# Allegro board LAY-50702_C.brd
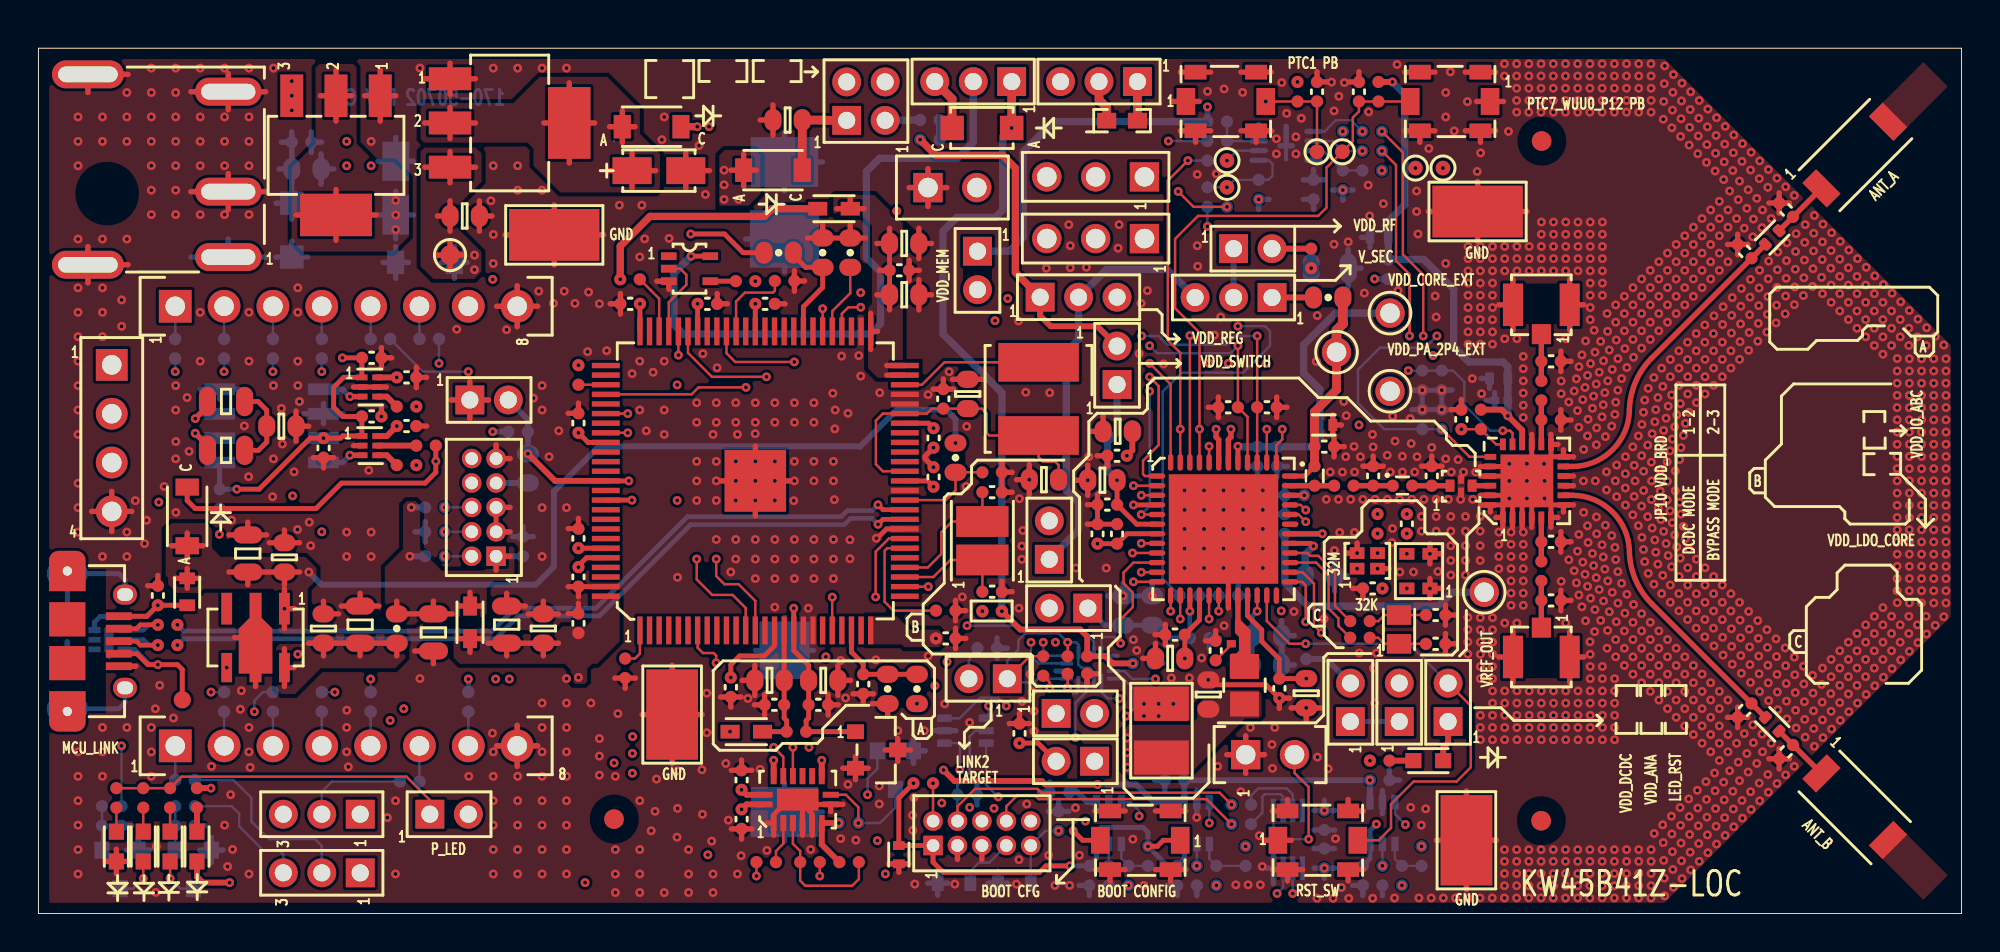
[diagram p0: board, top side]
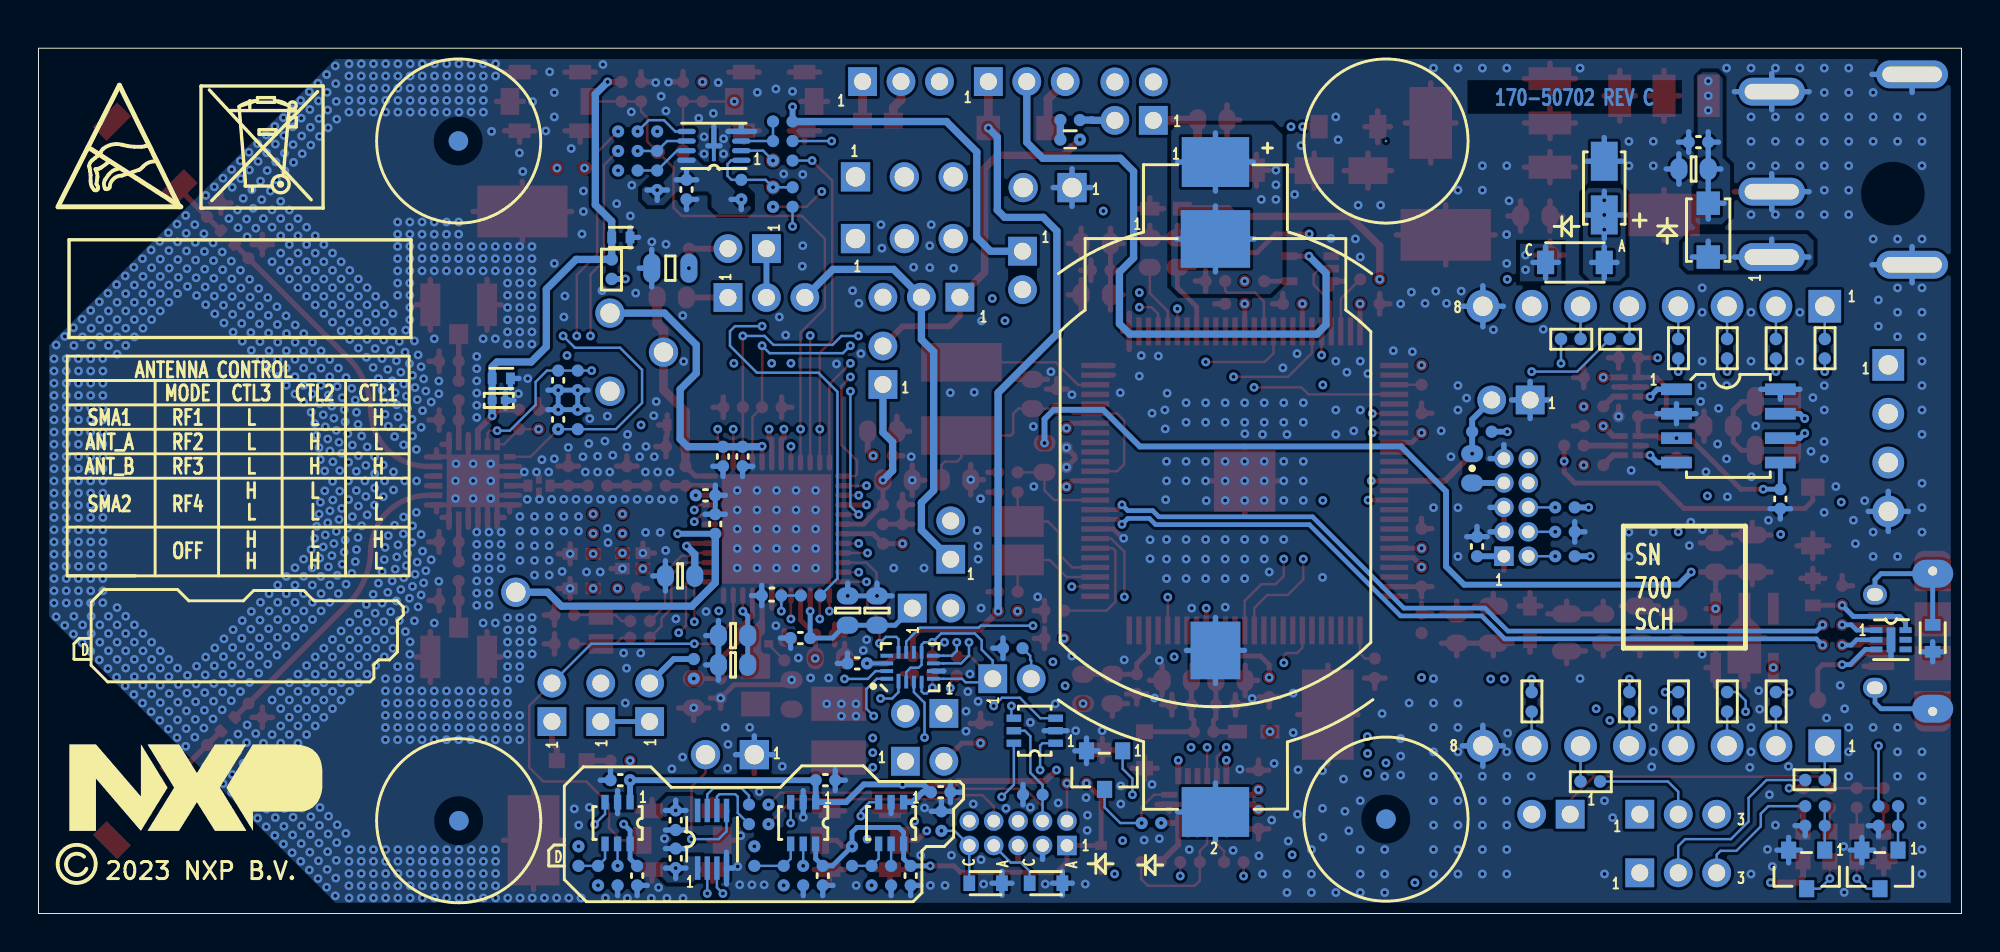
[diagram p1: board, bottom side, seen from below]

Outline 100 x 45 mm; copper layers: TOP, L2_GND_1, L3_INT_1, L4_INT_2, L5_GND_2, BOTTOM. Coordinates in mm from the lower left corner of the outline.
Outline path: 0,45 0,0 100,0 100,45 0,45

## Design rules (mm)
constraint set DEFAULT: min track width 0.127
net group CAN_H&L_DP_100_OHM: nets CAN_HI CAN_LO
net group CAN_RX&TX_DP_100_OHM: nets CAN_RX CAN_TX
net group CAN_XTND_RX&TX_DP_100_OHM: nets PTC4 PTC5
net group EXTAL32_DP: nets PTD4_XTAL32K PTD5_EXTAL32K
net group USB_DP_90_OHM: nets FL_USB1_DM FL_USB1_DP
net group XTAL_RF_DP: nets EXTAL_RF XTAL_RF

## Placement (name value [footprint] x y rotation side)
BMP1  BUMPER_312MIL  [BUMPER_RD_312MIL]  29.93 40.17 180 bottom
BMP2  BUMPER_312MIL  [BUMPER_RD_312MIL]  78.15 40.17 180 bottom
BMP3  BUMPER_312MIL  [BUMPER_RD_312MIL]  29.93 4.91 180 bottom
BMP4  BUMPER_312MIL  [BUMPER_RD_312MIL]  78.15 4.83 180 bottom
BT1  SMTU2450N-LF  [CON2_BH_CR2430]  38.8 22.18 270 bottom
BT2  S8421-45R  [BATTERY_HOLDER_2032_SM]  38.8 22.18 0 bottom
C1  1.1pF  [CC0402_25]  69.4 22.76 90 top
C2  2.5pF  [CC0402_25]  72.45 22.76 90 top
C3  15pF  [CC0402_ALT_NSP]  73.98 22.25 0 top
C5  22uF  [CC1210]  58.39 9.51 90 top
C6  0.01uf  [CC0603_OV]  60.83 11.39 90 top
C7  1uF  [CC0402_TOL0P2]  66.83 25.41 0 top
C8  47pF  [CC0402_25]  61.21 13.68 90 top
C9  10PF  [CC0402_25]  88.72 34.44 135 top
C10  1pF  [CC0402_25]  90.87 36.59 135 top
C11  10PF  [CC0402_25]  88.72 10.56 225 top
C12  1pF  [CC0402_25]  90.87 8.41 225 top
C13  4.7uF  [CC0603_OV]  58.85 13.27 180 top
C14  0.1UF  [CC0402_25]  59.1 14.51 180 top
C15  0.22uF  [CC0402_25]  64.81 20.26 90 bottom
C16  0.1UF  [CC0402_25]  63.39 23.77 270 bottom
C17  0.1UF  [CC0402_25]  64.4 23.77 270 bottom
C18  12pF  [CC0402_25]  66.86 24.28 0 top
C19  0.01uF  [CC0201]  76.06 26.69 180 bottom
C20  1uF  [CC0402_TOL0P2]  75.93 27.83 180 bottom
C21  3pF  [CC0402_25]  63.88 26.33 0 top
C22  3pF  [CC0402_25]  61.86 26.33 180 top
C23  10uF  [CC0603_OV]  22.16 36.27 0 top
C24  10UF  [CC3216]  32.26 38.63 0 top
C25  10uF  [CC0603_OV]  38.96 41.27 180 top
C26  0.1UF  [CC0402_25]  55.58 21.27 180 top
C27  4.7uF  [CC0603_OV]  55.33 22.54 180 top
C28  0.1UF  [CC0402_25]  56.09 19.74 90 top
C29  0.1UF  [CC0402_25]  55.07 19.74 90 top
C30  10uF  [CC0603_OV]  65.92 11.46 270 top
C31  0.1UF  [CC0402_25]  64.53 11.71 270 top
C32  4.7uF  [CC0603_OV]  56.12 25.08 180 top
C33  0.1UF  [CC0402_25]  56.09 23.81 180 top
C34  4.7uF  [CC0603_OV]  66.63 17.56 0 bottom
C35  0.1UF  [CC0402_25]  60.38 14.33 0 bottom
C36  4.7uF  [CC0603_OV]  57.92 15.76 90 bottom
C37  10uF  [CC0603_OV]  56.4 15.76 90 bottom
C38  4.7uF  [CC0603_OV]  63.88 12.93 0 bottom
C39  1.5uF  [CC0603_OV]  63.88 14.45 0 bottom
C40  12pF  [CC0402_25]  65.31 21.75 180 bottom
C41  22uF  [CC0805_OV]  67.14 33.56 0 bottom
C42  10uF  [CC0402_TOL0P2]  69.72 35.16 180 bottom
C43  1000pF  [CC0402_25]  61.88 16.54 0 bottom
C44  0.1UF  [CC0402_25]  66.3 37.65 270 bottom
C45  1000pF  [CC0402_25]  66.48 42.74 90 top
C46  1000pF  [CC0402_25]  68.67 42.74 90 top
C47  0.1UF  [CC0402_25]  69.38 16.91 180 top
C48  1000pF  [CC0402_25]  71.16 20.27 270 top
C49  12pF  [CC0402_25]  72.66 14.03 0 top
C50  12pF  [CC0402_25]  72.66 15.53 0 top
C51  4.7uF  [CC0603_OV]  26.25 14.82 90 top
C52  0.1UF  [CC0402_25]  34.78 31.71 0 top
C53  10uF  [CC0805_OV]  20.54 14.62 270 top
C54  10uF  [CC0805_OV]  24.35 15.03 90 top
C55  0.1UF  [CC0402_25]  36 11.77 270 top
C56  0.1UF  [CC0402_25]  47.18 14.31 0 top
C57  0.1UF  [CC0402_25]  46.54 24.73 270 top
C58  0.1UF  [CC0402_25]  37.78 31.71 0 top
C59  0.01UF  [CC0402_25]  30.77 31.71 180 top
C60  0.01UF  [CC0402_25]  28.08 25.51 90 top
C61  0.01UF  [CC0402_25]  28.08 19.51 90 top
C62  0.01UF  [CC0402_25]  28.08 15.09 90 top
C63  0.1UF  [CC0402_25]  38.27 10.86 180 top
C64  47pF  [CC0603_OV]  38.01 12.13 180 top
C65  47pF  [CC0603_OV]  48.32 27.02 90 top
C66  0.1UF  [CC0402_25]  47.05 26.77 90 top
C67  22uF  [CC0603_OV]  52.28 22.56 180 top
C68  22uF  [CC0603_OV]  45.02 34.85 0 top
C69  0.1UF  [CC0402_25]  44.77 33.45 0 top
C70  0.1UF  [CC0402_25]  40.55 10.86 0 top
C71  0.01uf  [CC0603_OV]  40.81 12.13 0 top
C72  47pF  [CC0603_OV]  45.02 32.18 0 top
C73  0.022UF  [CC0603_OV]  14.82 14.82 90 top
C74  10uF  [CC0805_OV]  16.73 15.03 90 top
C75  10uF  [CC0805_OV]  10.88 18.72 90 top
C76  0.022UF  [CC0603_OV]  12.79 18.52 90 top
C77  12pF  [CC0402_25]  49.59 21.91 0 top
C78  12pF  [CC0402_25]  49.59 16.74 0 top
C79  0.1UF  [CC0402_25]  46.54 22.7 90 top
C80  0.1UF  [CC0402_25]  28.08 17.51 270 top
C81  2.2UF  [CC0402_25]  6.21 16.54 90 top
C82  0.1UF  [CC0402_25]  42.89 11.93 270 top
C83  0.1UF  [CC0402_25]  25.19 19.09 90 bottom
C84  0.1UF  [CC0402_25]  57.42 13.01 0 bottom
C85  0.1UF  [CC0402_25]  66.86 4.85 270 bottom
C86  0.1UF  [CC0402_25]  66.86 2.87 90 bottom
C87  0.1UF  [CC0402_25]  53.09 6.31 180 bottom
C88  0.1UF  [CC0402_25]  54.65 1.97 270 bottom
C89  0.1UF  [CC0402_25]  69.74 6.94 0 bottom
C90  0.1UF  [CC0402_25]  68.87 1.97 270 bottom
C91  10uF  [CC0402_TOL0P2]  44.74 3.06 270 top
C92  0.1UF  [CC0402_25]  59.08 6.94 180 bottom
C93  0.1UF  [CC0402_25]  59.22 1.97 270 bottom
C94  0.1UF  [CC0402_25]  36.56 4.91 270 top
C95  0.1UF  [CC0402_25]  36.56 6.94 90 top
C97  10PF  [CC0402_25]  78.66 28.72 0 top
C98  10PF  [CC0402_25]  78.66 19.33 0 top
C99  10PF  [CC0402_25]  78.66 16.28 0 top
C100  100pF  [CC0402_25]  72.97 27.73 270 bottom
C101  100pF  [CC0402_25]  73.99 25.7 90 top
C102  100pF  [CC0402_25]  72.97 25.7 90 bottom
C103  0.1UF  [CC0402_25]  17.33 25.85 0 top
C104  0.1UF  [CC0402_25]  19.14 25.35 0 top
C105  0.1UF  [CC0402_25]  9.42 21.56 270 bottom
C106  0.1UF  [CC0402_25]  14.82 24.22 270 top
C107  10UF  [CC0603_OV]  13.93 38.72 0 bottom
C108  0.1UF  [CC0402_25]  13.68 40.12 0 bottom
C109  10UF  [CC3216]  18.58 37.73 90 bottom
C110  4700PF  [CC0603_OV]  12.63 25.35 180 top
C111  0.1UF  [CC0402_25]  17.33 28.9 0 top
C112  0.1UF  [CC0402_25]  19.14 27.88 0 top
C113  1000pF  [CC0402_25]  51.01 9.37 90 top
D1  RB160M-30  [PMDU_SOD123]  31.88 40.92 180 top
D2  RB160M-30  [PMDU_SOD123]  38.19 38.66 180 top
D3  SML-D14U2WT86C  [LED_0603]  72.27 7.95 0 top
D4  RB160M-30  [PMDU_SOD123]  7.73 20.65 270 top
D7  RED  [LED_0603]  8.24 3.49 270 top
D8  PNS40010ER  [SOD123W]  13.17 35.54 270 bottom
D12  PMEG1020EH  [SOD123LF]  49.06 40.85 0 top
D13  PESD3V3S1UB  [SOD523]  47.61 1.58 180 bottom
D14  PESD3V3S1UB  [SOD523]  50.75 1.58 180 bottom
D15  PESD3V3L5UY  [SOT-363_0P65_SMT]  48.19 9.51 0 bottom
D16  RB160M-30  [PMDU_SOD123]  20.1 33.86 180 bottom
E1  ANTENNA_2400MHZ  [ANTENNA-2450]  94.45 39.45 45 top
E2  ANTENNA_2400MHZ  [ANTENNA-2450]  94.45 5.55 315 top
J1  CON_1X8  [CON_1X8_SKT_2P54_TH]  7.11 31.58 90 top
J2  CON_1X8  [CON_1X8_SKT_2P54_TH]  7.11 8.72 90 top
J3  ZX62D-B-5PA8(30)  [CON9_MICROB_USB_SHELL_TH]  1.5 14.16 270 top
J4  HDR 2X5  [HDR205_50_TH]  23.8 18.58 90 top
J5  HDR 2X5  [HDR205_50_TH]  46.52 3.54 0 top
J7  20279-001E  [COAX_3P_SM_20279]  78.15 31.66 270 top
J8  20279-001E  [COAX_3P_SM_20279]  78.15 13.34 90 top
J9  CON PWR 3  [CON3_PWR_JACK_TH_PJ051A]  9.87 34.14 0 top
J10  HDR 1X4 RA  [CON_HDR_4M_100_TH_RA]  3.81 28.53 270 top
JP1  MTMM-102-06-G-S-236  [HDR102_TMM]  56.09 27.51 270 top
JP2  HDR 2X2  [HDR202_TMM]  42.03 41.25 0 top
JP3  HDR_1X3  [HDR103_78MIL]  52.09 32.05 180 top
JP4  MTMM-102-06-G-S-236  [HDR102_TMM]  54.56 15.88 0 top
JP6  MTMM-102-06-G-S-236  [HDR102_TMM]  62.15 34.58 180 top
JP7  MTMM-102-06-G-S-236  [HDR102_TMM]  68.22 9.98 270 top
JP8  MTMM-102-06-G-S-236  [HDR102_TMM]  52.56 18.42 270 top
JP9  MTMM-102-06-G-S-236  [HDR102_TMM]  70.76 9.98 270 top
JP10  HDR_1X3  [HDR103_78MIL]  64.15 32.04 0 top
JP11  MTMM-102-06-G-S-236  [HDR102_TMM]  73.3 9.98 270 top
JP12  MTMM-102-06-G-S-236  [HDR102_TMM]  22.43 26.71 180 top
JP13  HDR 1X3  [CONN_HDR_3X1]  57.51 35.1 270 top
JP14  HDR 1X3  [CONN_HDR_3X1]  57.51 38.31 270 top
JP16  MTMM-102-06-G-S-236  [HDR102_TMM]  54.92 7.92 0 top
JP17  MTMM-102-06-G-S-236  [HDR102_TMM]  50.38 12.21 0 top
JP18  HDR_1X3  [HDR103_78MIL]  50.61 43.27 0 top
JP19  HDR_1X3  [HDR103_78MIL]  57.15 43.27 0 top
JP21  HDR 1X2  [HDR102_338H]  46.25 37.75 90 top
JP22  HDR 1X2  [HDR102_338H]  62.77 8.26 90 top
JP23  HDR_1X3  [HDR103_78MIL]  16.73 2.12 0 top
JP24  HDR_1X3  [HDR103_78MIL]  16.73 5.17 0 top
JP25  MTMM-102-06-G-S-236  [HDR102_TMM]  52.92 10.41 180 top
JS1  HDR 1X2  [SH_HDR102_2MM_BOTTOM]  48.83 34.44 90 top
JS2  HDR 1X2  [SH_HDR102_2MM_BOTTOM]  20.35 5.17 180 top
L1  1uH  [IND_0805]  62.71 11.87 270 top
L2  15nH  [IND_0402_POL]  66.36 22.76 270 top
L3  0  [RC0402_25]  67.88 22.25 0 top
L4  600OHM  [IND_1P8X1MM_SM]  22.44 15.15 270 top
L5  600OHM  [IND_1P8X1MM_SM]  36.81 9.46 0 top
L6  4.7uH  [IND_5P2X5P2]  52 26.76 270 top
L7  600OHM  [IND_1P8X1MM_SM]  41.37 36.65 0 top
L8  330 OHM  [IND_1608]  7.73 16.73 90 top
L9  330 OHM  [IND_1608]  1.5 14.31 270 bottom
L10  1.5nH  [IND_0402_POL]  70.93 22.25 0 top
L11  2.2nH  [IND_0402_L]  90.16 35.16 45 top
L12  2.2nH  [IND_0402_L]  90.16 9.84 315 top
L13  1800 OHM  [IND_0402]  46.35 40.25 180 bottom
LED1  SML-D14U2WT86C  [LED_0603]  6.85 3.49 270 top
LED2  LED_YEL  [LED_0603]  5.45 3.49 270 top
LED3  LED_GREEN  [LED_0603]  4.05 3.49 270 top
NOREF  -  []  79.3 21.25 90 top
NOREF#2  -  []  79.45 20.45 0 top
NOREF#3  -  []  89.8 10.2 0 top
NOREF#4  -  []  30.9 14.17 0 top
NOREF#5  -  []  22.94 16.05 0 top
NOREF#6  -  []  41.2 5.68 90 top
NOREF#7  -  []  40.47 37.15 90 top
NOREF#8  -  []  66.36 25.41 0 top
NOREF#9  -  []  61.37 23.46 0 top
NOREF#10  -  []  38.67 37.15 0 top
NOREF#11  -  []  -349.15 214.49 0 top
NOREF#12  -  []  38.8 9.44 90 top
NOREF#13  -  []  68.1 2.28 90 top
NOREF#14  -  []  68.68 5.46 90 top
NOREF#15  -  []  64.45 3.81 0 top
NOREF#16  -  []  34.3 8 90 top
NOREF#17  -  []  6.2 17.91 90 top
NOREF#18  -  []  77.73 27.48 90 top
NOREF#19  -  []  90.01 9.78 0 top
NOREF#20  -  []  79.52 11.97 0 top
NOREF#21  -  []  40.73 4.71 90 top
NOREF#22  -  []  35.96 9.46 0 top
NOREF#23  -  []  61.37 23.46 0 top
NOREF#24  -  []  11.29 14.35 0 top
NOREF#25  -  [unnamed#2]  78.14 4.83 180 top
NOREF#26  -  []  76.53 27.48 0 top
NOREF#27  -  []  89.52 34.31 0 top
NOREF#28  -  []  70.75 14.03 90 top
NOREF#29  -  []  7.11 8.72 0 top
NOREF#30  -  []  55.72 5.34 0 top
NOREF#31  -  []  35.91 9.96 0 top
NOREF#32  -  []  13.59 15.65 0 top
NOREF#33  -  []  63.89 40.58 90 top
NOREF#34  -  []  44.39 3.66 0 top
NOREF#35  -  []  52 24.86 90 top
NOREF#36  -  []  64.95 2.28 0 top
NOREF#37  -  []  68.25 17.69 90 top
NOREF#38  -  []  73.98 21.93 90 top
NOREF#39  -  []  71.38 13.73 0 top
NOREF#40  -  []  76.67 31.66 0 top
NOREF#41  -  []  29.5 28.5 0 top
NOREF#42  -  []  78.15 14.87 0 top
NOREF#43  -  []  90.01 9.78 90 top
NOREF#44  -  []  71.26 37.28 90 top
NOREF#45  -  []  100 0 90 top
NOREF#46  -  []  71.52 34.81 90 top
NOREF#47  -  []  9.79 12.79 90 top
NOREF#48  -  []  60.17 40.71 0 top
NOREF#49  -  []  66.23 25.06 0 top
NOREF#50  -  []  35.91 8.96 90 top
NOREF#51  -  []  49.4 29.36 0 top
NOREF#52  -  []  61.31 4.26 90 top
NOREF#53  -  []  61.62 20 0 top
NOREF#54  -  []  45.69 2.4 0 top
NOREF#55  -  []  54.6 29.36 90 top
NOREF#56  -  []  62.77 8.26 0 top
NOREF#57  -  []  71.83 40.71 90 top
NOREF#58  -  []  23.8 18.58 90 top
NOREF#59  -  []  71.16 18.71 0 top
NOREF#60  -  []  58.39 4.26 0 top
NOREF#61  -  []  73.4 22.25 0 top
NOREF#62  -  []  55.15 -1.14 90 top
NOREF#63  -  []  38.23 7.15 0 top
NOREF#64  -  []  41.28 4.63 0 top
NOREF#65  -  []  82.27 11.97 90 top
NOREF#66  -  []  76.67 13.34 0 top
NOREF#67  -  []  68.25 17.69 0 top
NOREF#68  -  []  4.5 11.74 90 top
NOREF#69  -  []  45.69 2.4 90 top
NOREF#70  -  []  75.18 37.85 90 top
NOREF#71  -  []  18.19 15.65 90 top
NOREF#72  -  []  38.8 22.18 90 top
NOREF#73  -  []  72.36 16.91 90 top
NOREF#74  -  []  68.68 8.76 0 top
NOREF#75  -  []  79.52 33.03 90 top
NOREF#76  -  []  45.05 27 90 top
NOREF#77  -  []  58.16 19.75 90 top
NOREF#78  -  []  58.28 15.5 90 top
NOREF#79  -  []  78.65 20.6 90 top
NOREF#80  -  []  71.33 42.23 0 top
NOREF#81  -  []  66.96 37.28 0 top
NOREF#82  -  []  89.8 34.8 0 top
NOREF#83  -  []  4.18 12.86 90 top
NOREF#84  -  []  58.12 16.5 0 top
NOREF#85  -  []  46.25 37.75 0 top
NOREF#86  -  []  24.94 17.76 0 top
NOREF#87  -  []  32.2 34.92 0 top
NOREF#88  -  []  24.47 36.64 0 top
NOREF#89  -  []  68.57 17.94 0 top
NOREF#90  -  []  76.67 31.66 0 top
NOREF#91  -  []  38.8 13.68 90 top
NOREF#92  -  []  78.29 6.16 90 top
NOREF#93  -  []  50.25 36.29 90 top
NOREF#94  -  []  23.8 18.58 90 top
NOREF#95  -  []  75.5 23.75 0 top
NOREF#96  -  []  45.59 3.66 90 top
NOREF#97  -  []  22.44 14.3 90 top
NOREF#98  -  []  22.94 15.05 90 top
NOREF#99  -  []  75.6 6.16 0 top
NOREF#100  -  []  59.67 42.23 0 top
NOREF#101  -  []  -385.38 -304.33 0 top
NOREF#102  -  []  83.55 20.45 90 top
NOREF#103  -  []  67.43 25.06 90 top
NOREF#104  -  []  78.15 24.4 0 top
NOREF#105  -  []  -1.3 23.51 0 top
NOREF#106  -  []  9.42 32.24 0 top
NOREF#107  -  []  50.85 -1.14 0 top
NOREF#108  -  []  61.62 20 90 top
NOREF#109  -  []  27.16 36.64 90 top
NOREF#110  -  []  36.78 30.28 0 top
NOREF#111  -  []  98.41 35.04 0 top
NOREF#112  -  []  24.94 17.76 90 top
NOREF#113  -  []  44.74 2.59 90 top
NOREF#114  -  []  63.45 40.67 0 top
NOREF#115  -  []  63.32 40.71 90 top
NOREF#116  -  []  76.77 33.03 0 top
NOREF#117  -  []  75.46 27.83 0 top
NOREF#118  -  []  12.22 32.24 90 top
NOREF#119  -  [unnamed#2]  29.93 4.91 180 top
NOREF#120  -  []  38.23 7.15 0 top
NOREF#121  -  []  -0.57 -80.18 0 top
NOREF#122  -  []  55.22 3.81 0 top
NOREF#123  -  []  73.48 13.73 90 top
NOREF#124  -  []  70.32 34.81 0 top
NOREF#125  -  []  22.53 18.58 0 top
NOREF#126  -  []  31.61 8 0 top
NOREF#127  -  []  4.18 13.51 90 top
NOREF#128  -  []  73.45 21.98 0 top
NOREF#129  -  []  43.88 4.63 90 top
NOREF#130  -  []  89.52 34.31 90 top
NOREF#131  -  []  46.52 3.54 0 top
NOREF#132  -  []  7.11 8.72 0 top
NOREF#133  -  [unnamed#2]  78.16 40.17 180 top
NOREF#134  -  []  40.52 36.65 0 top
NOREF#135  -  []  0 45 0 top
NOREF#136  -  []  37.28 22.5 90 top
NOREF#137  -  []  69.24 35.16 0 top
NOREF#138  -  []  68.57 17.94 90 top
NOREF#139  -  []  74.5 21.98 90 top
NOREF#140  -  []  7.11 8.72 0 top
NOREF#141  -  []  71.83 43.76 0 top
NOREF#142  -  []  72.49 37.85 0 top
NOREF#143  -  []  65.12 16.5 90 top
NOREF#144  -  []  46.52 3.54 90 top
NOREF#145  -  []  59.59 40.58 0 top
NOREF#146  -  []  46.52 3.54 0 top
NOREF#147  -  []  55.72 2.28 90 top
NOREF#148  -  []  44.28 15.5 0 top
NOREF#149  -  []  44.79 39.21 0 top
NOREF#150  -  []  98.01 2.56 180 bottom
NOREF#151  -  []  91.55 36.69 180 bottom
NOREF#152  -  []  98.38 4.3 180 bottom
NOREF#153  -  []  98.97 36.75 180 bottom
NOREF#154  -  []  98.41 29.96 180 bottom
NOREF#155  -  [unnamed#2]  78.14 4.83 180 bottom
NOREF#156  -  [unnamed#2]  29.93 4.91 180 bottom
NOREF#157  -  [unnamed#2]  78.16 40.17 180 bottom
Q1  BSH111BK  [SOT23_A]  8.05 2.29 0 bottom
Q2  BSH111BK  [SOT23_A]  4.24 2.29 0 bottom
Q3  BSS138P  [SOT23_A]  44.56 7.46 0 bottom
R1  22  [RC0201]  62.37 14.03 180 top
R8  100  [RC0402_25]  59.85 16.54 180 bottom
R9  10K  [RC0402_25]  65.47 42.74 270 top
R10  10K  [RC0402_25]  67.83 40.17 270 bottom
R11  10K  [RC0402_25]  63.45 37.65 90 bottom
R12  0  [RC0402_25]  69.35 39.66 180 bottom
R13  0  [RC0402_25]  61.29 39.16 0 bottom
R14  0  [RC0402_25]  69.35 40.67 180 bottom
R15  0  [RC0402_25]  61.29 40.17 0 bottom
R16  0  [RC0402_25]  60.79 37.26 90 bottom
R17  10K  [RC0402_25]  69.68 42.74 270 top
R18  0  [RC0402_25]  69.35 38.64 180 bottom
R19  10K  [RC0402_25]  61.29 41.19 0 bottom
R20  10K  [RC0402_25]  67.83 38.13 90 bottom
R21  0  [RC0402_25]  61.8 37.26 90 bottom
R22  100  [RC0402_25]  6.85 6.01 270 top
R23  100  [RC0402_25]  5.45 6.01 270 top
R24  100  [RC0402_25]  69.74 7.95 0 top
R25  510  [RC0402_25]  4.05 6.01 270 top
R26  0  [RC0402_25]  7.62 5.58 180 bottom
R27  0  [RC0402_25]  3.81 5.58 0 bottom
R28  10K  [RC0402_25]  7.62 4.57 180 bottom
R29  10K  [RC0402_25]  3.81 4.57 180 bottom
R30  0  [RC0402_25]  68.72 14.34 0 top
R31  0  [RC0402_25]  68.72 15.21 0 top
R32  0  [RC0402_25]  69.63 20.27 270 top
R33  1K  [RC0402_25]  39.41 9.46 0 top
R34  0  [RC0603_OV]  18.63 14.82 90 top
R37  10K  [RC0603_OV]  47.69 23.71 270 top
R38  0  [RC0603_OV]  40.78 34.37 270 top
R39  0  [RC0402_25]  6.72 15.02 0 top
R40  0  [RC0402_25]  6.72 13.96 0 top
R41  20K  [RC0402_25]  49.59 22.94 0 top
R42  0  [RC0603_OV]  38.49 34.37 180 top
R43  2.0K  [RC0603_OV]  45.68 11.68 90 top
R44  2.0K  [RC0603_OV]  44.16 11.68 270 top
R45  60.4  [RC0805_OV]  9.75 24.09 0 top
R46  100K  [RC0402_25]  20.62 21.12 0 bottom
R47  100K  [RC0402_25]  20.62 18.58 0 bottom
R48  100K  [RC0402_25]  24.94 25.06 0 bottom
R50  510  [RC0402_25]  8.24 6.01 270 top
R51  0  [RC0603_OV]  25.45 23.15 270 bottom
R53  100K  [RC0402_25]  20.62 19.85 180 bottom
R63  10  [RC0402_25]  62.55 5.67 180 bottom
R64  10  [RC0402_25]  62.55 4.65 180 bottom
R65  0  [RC0402_25]  52.25 12.87 90 top
R66  100K  [RC0402_25]  54.03 12.47 0 top
R67  100K  [RC0402_25]  54.03 13.38 0 top
R68  160K  [RC0402_25]  57.69 2.99 270 bottom
R69  100  [RC0402_25]  56.68 1.97 270 bottom
R70  2.2K  [RC0402_25]  55.66 1.97 270 bottom
R71  10  [RC0402_25]  49.34 13.8 0 bottom
R72  100K  [RC0402_25]  71.92 2.99 270 bottom
R73  100  [RC0402_25]  70.9 1.97 270 bottom
R74  2.2K  [RC0402_25]  69.89 1.97 270 bottom
R75  10K  [RC0402_25]  46.01 6.77 0 top
R76  100K  [RC0402_25]  62.77 2.99 270 bottom
R77  2.2K  [RC0402_25]  53.05 4.81 90 bottom
R78  100  [RC0402_25]  61.25 1.97 270 bottom
R79  10K  [RC0402_25]  48.3 6.18 0 bottom
R80  2.2K  [RC0402_25]  60.23 1.97 270 bottom
R81  1K  [RC0402_25]  28.08 28.01 90 top
R83  1K  [RC0402_25]  36.77 32.89 0 top
R84  100  [RC0402_25]  37.84 2.68 180 top
R85  100  [RC0402_25]  40.12 2.68 0 top
R86  10K  [RC0402_25]  42.13 4.71 0 bottom
R89  0  [RC0603_OV]  67.07 32.04 180 top
R91  100K  [RC0402_25]  75.01 25.7 270 top
R92  0  [RC0402_25]  78.15 27.19 90 top
R93  0  [RC0402_25]  78.15 17.81 270 top
R94  100K  [RC0402_25]  71.96 27.73 270 bottom
R95  100K  [RC0402_25]  71.96 25.7 90 bottom
R96  0  [RC0603_OV]  42.21 34.37 90 top
R97  4.7K  [RC0402_25]  20.16 24.33 180 top
R98  0  [RC0402_25]  19.14 23.32 0 top
R99  60.4  [RC0805_OV]  9.75 26.63 180 top
R100  0  [RC0402_25]  19.14 26.37 0 top
R101  100K  [RC0402_25]  42.15 2.68 0 top
R102  1K  [RC0402_25]  30.76 32.98 180 top
R104  1K  [RC0402_25]  38.8 32.9 0 top
R105  1K  [RC0402_25]  30.51 12.75 270 top
R106  1K  [RC0402_25]  47.18 15.75 0 top
R107  10  [RC0402_25]  46.35 41.27 0 bottom
R108  3.3  [RC0402_25]  65.92 12.73 270 bottom
R109  3.3  [RC0402_25]  66.18 34.07 270 top
R110  50  [RC0402_25]  78.66 25.67 0 top
SH1  0  [SH0402]  9.65 29.37 270 bottom
SH2  0  [SH0402]  7.11 29.37 270 bottom
SH3  0  [SH0402]  7.62 6.94 180 bottom
SH4  0  [SH0402]  12.19 29.37 270 bottom
SH5  0  [SH0402]  9.65 11.01 270 bottom
SH6  0  [SH0402]  14.73 29.37 270 bottom
SH7  0  [SH0402]  12.19 11.01 270 bottom
SH8  0  [SH0402]  17.78 29.88 0 bottom
SH9  0  [SH0402]  14.73 11.01 270 bottom
SH10  0  [SH0402]  20.32 29.88 0 bottom
SH11  0  [SH0402]  17.27 11.01 270 bottom
SH12  0  [SH0402]  70.19 33.51 90 bottom
SH13  0  [SH0402]  19.3 6.87 0 bottom
SH14  0  [SH0402]  22.35 11.01 270 bottom
SH15  0  [SH0402]  49.59 15.72 0 top
SH19  0  [SH0603]  56.35 41.23 0 top
SW1  TL1015AF160QG  [SW2_SPST_4X3_SM]  66.53 3.81 0 top
SW2  TL1015AF160QG  [SW2_SPST_4X3_SM]  61.74 42.23 0 top
SW3  TL1015AF160QG  [SW2_SPST_4X3_SM]  73.41 42.23 180 top
SW4  TL1015AF160QG  [SW2_SPST_4X3_SM]  57.3 3.81 180 top
TP1  TESTLOOP_LP  [TEST_LOOP]  70.28 31.22 0 top
TP2  TESTLOOP_LP  [TEST_LOOP]  75.18 16.71 0 top
TP3  TESTLOOP_LP  [TEST_LOOP]  67.5 29.19 0 top
TP4  TESTLOOP_LP  [TEST_LOOP]  70.28 27.16 0 top
TP7  -  [TPAD_040]  21.4 34.24 0 top
TP8  -  [TPAD_030]  71.6 38.77 0 top
TP9  -  [TPAD_030]  66.48 39.62 180 top
TP10  -  [TPAD_030]  73.03 38.77 0 top
TP11  -  [TPAD_030]  61.8 37.77 0 top
TP12  -  [TPAD_030]  67.8 39.62 0 top
TP13  -  [TPAD_030]  61.8 39.16 180 top
TP15  TP_2P7X4P7  [TP_2P7X4P7MM]  74.25 3.81 180 top
TP16  TP_2P7X4P7  [TP_2P7X4P7MM]  32.95 10.35 0 top
TP17  TP_2P7X4P7  [TP_2P7X4P7MM]  26.82 35.29 270 top
TP18  TP_2P7X4P7  [TP_2P7X4P7MM]  74.84 36.51 270 top
TP21  TP_35MIL  [TESTPOINT_35MIL]  7.48 11.11 0 top
U1  KW45B41Z  [QFN_48_0P5_7X7_5P7EP]  61.62 20 0 top
U2  HSWA4-63DR  [QFN24_0P5_SQ4_EP2P75]  77.4 22.5 90 top
U4  NCP1117ST33T3G  [SOT223]  24.5 41.11 270 top
U5  AT25XE161D-MAHN-T  [UDFN8_0P5_3X2MM]  64.88 39.92 0 bottom
U6  LPC55S69JBD100  [HLQFP100_0P5_14X14]  37.28 22.5 90 top
U7  LM4040C30IDBZR  [SOT23-3]  43.58 8.51 270 top
U8  XC6227C331PR-G  [SOT89-5]  11.29 14.35 180 top
U9  RClamp0854P.TCT  [SLP1616P6]  3.67 14.24 270 bottom
U10  74LVC2T45DC  [SSOP8_DCU]  64.97 3.86 180 bottom
U11  NX3DV2567GU  [PQFN16_0P4_2P65X1P85]  54.68 12.81 180 bottom
U12  74LVC1T45GW,125  [SOT-363_0P65_SMT]  55.66 4.71 270 bottom
U13  74LVC1T45GW,125  [SOT-363_0P65_SMT]  69.89 4.71 270 bottom
U14  74LVC1T45GW,125  [SOT-363_0P65_SMT]  60.23 4.71 270 bottom
U15  74LVC1G07GW-Q100  [SC70-5]  33.86 33.54 270 top
U16  74AVC4TD245BQ  [DHVQFN16_0P5_3P6X2P6]  39.48 5.93 90 top
U17  74LVCH1T45  [UDFN6_1X1P5MM]  17.24 24.33 0 top
U18  NCP1117ST50T3G  [SOT223]  15.47 39.43 180 top
U19  TJA1057GT/3  [SO8_1P27_4X5]  12.12 25.36 180 bottom
U20  74LVCH1T45  [UDFN6_1X1P5MM]  17.24 27.38 0 top
U21  DEA102025LT-6313A1  [FILTER_1P05X0P55_SM_B]  73.98 22.25 0 top
Y1  32MHz  [XTAL4_1P6X1P2]  69.1 18.34 0 top
Y2  32.768 kHz  [XTAL2_2X1P2_SM]  70.75 14.78 90 top
Y3  32.00MHZ  [OSC4_2P1X1P7MM_SM]  71.76 17.81 90 top
Y4  16MHz  [XTAL2_3P3X2P6]  49.08 19.39 90 top

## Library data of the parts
BMP1-BMP4 = Bumper
BT1 BT2 = BATTERY
C1-C3 C5-C8 C10 C12-C18 C20-C23 C25-C95 C100-C108 C110-C113 = CAP_NP
C9 C11 C97-C99 = CAP_NP: tolerance: 5%
C19 = CAP_NP: Tolerance: TOLERANCE; User Part Number: 150-80313
C24 C109 = CAP_POL
D1 D2 D4 D12 D16 = DIODE_SCHTKY
D3 D7 LED1-LED3 = LED
D8 = DIODE
D13 D14 = DIODE_TVS
D15 = DIODE_ARRAY_5CH
E1 E2 = ANTENNA_2P4GHZ
J1 J2 = CONN_HDR_8X1
J3 = MICRO_USB_CONN_9PIN
J4 J5 = CONN_HDR_5X2
J7 J8 = UFL
J9 = DC_POWER_JACK_SHD
J10 = CONN_HDR_4X1
JP1 JP4 JP6-JP9 JP11 JP12 JP16 JP17 JP21 JP22 JP25 JS1 JS2 = CONN_HDR_2X1
JP2 = CONN_HDR_2X2
JP3 JP10 JP13 JP14 JP18 JP19 JP23 JP24 = CONN_HDR_3X1
L1 L4-L7 L11 L12 = INDUCTOR
L2 L10 = INDP
L3 R1 R8 R10 R12-R16 R18-R34 R37-R48 R50 R51 R53 R63-R81 R83-R85 R89 R91-R96 R98-R102 R104-R110 = RES
L8 L9 L13 = BEAD
Q1 Q2 = NMOS_2N7002BKW_3P
Q3 = MOSFET_N
R9 R11 R17 R97 = RES: tolerance: 1%
R86 = RES: tolerance: 5%
SH1-SH15 SH19 = RES_SHORT-2
SW1-SW4 = SW_SPNO_2P_GND6P
TP1-TP4 TP7-TP13 = TESTLOOP
TP15-TP18 = TEST_POINT
TP21 = T POINT R: Tolerance: TOLERANCE; User Part Number: 510-75618
U1 = KW45B41Z_48EP
U2 = HSWA4-63DR
U4 U18 = LD1117AS18
U5 = AT25XE161D_8P_EP
U6 = LPC55S69JB_HLQFP100
U7 = LM4040_SOT23
U8 = XC6227C_5P
U9 = RCLAMP1654P_NEW
U10 = 74LVC2T45DC_8P
U11 = NX3DV2567GU_XQFN_16P
U12-U14 U17 U20 = 74LVCH1T45_6P
U15 = 74AUP1G07GW
U16 = 74AVC4TD245BQ_DHVQFN16
U19 = TJA1057GT3_8P
U21 = B9014_4P
Y1 = XTAL_13
Y2 Y4 = XTAL
Y3 = O4-0

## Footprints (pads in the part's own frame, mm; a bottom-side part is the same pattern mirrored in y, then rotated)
ANTENNA-2450
  rect 1.016x1.803 smd: 1(-2.45,0) 2(2.45,0)
BATTERY_HOLDER_2032_SM
  rect 3.607x2.997 smd: 1(0,-12.9)
  rect 2.591x2.997 smd: 2(0,8.5)
BUMPER_RD_312MIL
  round 0.127 smd: 1(0,0)
CC0201
  rect 0.47x0.381 smd: 1(-0.343,0) 2(0.343,0)
CC0402_25
  round 0.635 smd: 1(-0.508,0) 2(0.508,0)
CC0402_ALT_NSP
  rect 0.457x0.635 smd: 1(-0.575,0) 2(0.575,0)
CC0402_TOL0P2
  rect 0.457x0.61 smd: 1(-0.475,0) 2(0.475,0)
CC0603_OV
  oval 0.889x1.143 smd: 1(-0.762,0) 2(0.762,0)
CC0805_OV
  oval 0.889x1.524 smd: 1(-0.965,0) 2(0.965,0)
CC1210
  rect 1.778x2.845 smd: 1(-1.397,0) 2(1.397,0)
CC3216
  rect 2.032x1.397 smd: 1(-1.397,0) 2(1.397,0)
COAX_3P_SM_20279
  rect 1.041x0.991 smd: 1(1.525,0)
  rect 2.21x1.041 smd: 2(0,1.475) 3(0,-1.475)
CON2_BH_CR2430
  rect 2.591x3.505 smd: 1(-16.9,0) 2(16.9,0)
CON3_PWR_JACK_TH_PJ051A
  round 0 hole 2.54 unplated: (-6.3,3.3)
  oval 3.454x1.448 hole 2.819x0.813: 1(0,0) 2(0,8.6) 3(0,3.4)
  oval 3.734x1.448 hole 3.099x0.813: SH1(-7.3,9.5) SH2(-7.3,-0.4)
CON9_MICROB_USB_SHELL_TH
  rect 1.778x1.88 smd: (-1.139,0) (1.139,0)
  rect 0.406x1.346 smd: 1(-1.3,2.677) 2(-0.65,2.677) 3(0,2.677) 4(0.65,2.677) 5(1.3,2.677)
  oval 1.041x1.245 hole 0.66x0.838: 6(-2.425,3) 7(2.425,3)
  custom 0.475x0.475 hole 1.499x0.813: 8(-3.65,0) 9(3.65,0)
CON_1X8_SKT_2P54_TH
  rect 1.702x1.702 hole 1.016: 1(0,0)
  round 1.702 hole 1.016: 2(0,-2.54) 3(0,-5.08) 4(0,-7.62) 5(0,-10.16) 6(0,-12.7) 7(0,-15.24) 8(0,-17.78)
CON_HDR_4M_100_TH_RA
  rect 1.651x1.651 hole 1.016: 1(0,0)
  round 1.651 hole 1.016: 2(2.54,0) 3(5.08,0) 4(7.62,0)
CONN_HDR_3X1
  rect 1.524x1.524 hole 1.016: 1(0,0)
  round 1.524 hole 1.016: 2(0,-2.54) 3(0,-5.08)
DHVQFN16_0P5_3P6X2P6
  rect 0.305x0.838 smd: 1(-0.25,1.719) 8(-0.25,-1.719) 9(0.25,-1.719) 16(0.25,1.719)
  rect 0.838x0.305 smd: 2(-1.219,1.25) 3(-1.219,0.75) 4(-1.219,0.25) 5(-1.219,-0.25) 6(-1.219,-0.75) 7(-1.219,-1.25) 10(1.219,-1.25) 11(1.219,-0.75) 12(1.219,-0.25) 13(1.219,0.25) 14(1.219,0.75) 15(1.219,1.25)
  rect 1.143x2.159 smd: 17(0,0)
FILTER_1P05X0P55_SM_B
  rect 0.457x0.305 smd: 1(-0.575,0) 3(0.575,0)
  rect 0.305x0.457 smd: 2(0,-0.325) 4(0,0.325)
HDR102_338H
  rect 1.524x1.524 hole 1.016: 1(0,0)
  round 1.524 hole 1.016: 2(0,-2.54)
HDR102_TMM
  rect 1.499x1.499 hole 0.889: 1(0,0)
  round 1.499 hole 0.889: 2(-2,0)
HDR103_78MIL
  rect 1.499x1.499 hole 0.889: 1(0,0)
  round 1.499 hole 0.889: 2(-2,0) 3(-4,0)
HDR202_TMM
  rect 1.499x1.499 hole 0.889: 1(0,0)
  round 1.499 hole 0.889: 2(0,2) 3(2,0) 4(2,2)
HDR205_50_TH
  rect 1.016x1.016 hole 0.66: 1(0,0)
  round 1.016 hole 0.66: 2(0,1.27) 3(1.27,0) 4(1.27,1.27) 5(2.54,0) 6(2.54,1.27) 7(3.81,0) 8(3.81,1.27) 9(5.08,0) 10(5.08,1.27)
HLQFP100_0P5_14X14
  rect 1.448x0.279 smd: 1(-7.775,6) 2(-7.775,5.5) 3(-7.775,5) 4(-7.775,4.5) 5(-7.775,4) 6(-7.775,3.5) 7(-7.775,3) 8(-7.775,2.5) 9(-7.775,2) 10(-7.775,1.5) 11(-7.775,1) 12(-7.775,0.5) 13(-7.775,0) 14(-7.775,-0.5) 15(-7.775,-1) 16(-7.775,-1.5) 17(-7.775,-2) 18(-7.775,-2.5) 19(-7.775,-3) 20(-7.775,-3.5) 21(-7.775,-4) 22(-7.775,-4.5) 23(-7.775,-5) 24(-7.775,-5.5) 25(-7.775,-6) 51(7.775,-6) 52(7.775,-5.5) 53(7.775,-5) 54(7.775,-4.5) 55(7.775,-4) 56(7.775,-3.5) 57(7.775,-3) 58(7.775,-2.5) 59(7.775,-2) 60(7.775,-1.5) 61(7.775,-1) 62(7.775,-0.5) 63(7.775,0) 64(7.775,0.5) 65(7.775,1) 66(7.775,1.5) 67(7.775,2) 68(7.775,2.5) 69(7.775,3) 70(7.775,3.5) 71(7.775,4) 72(7.775,4.5) 73(7.775,5) 74(7.775,5.5) 75(7.775,6)
  rect 0.279x1.448 smd: 26(-6,-7.775) 27(-5.5,-7.775) 28(-5,-7.775) 29(-4.5,-7.775) 30(-4,-7.775) 31(-3.5,-7.775) 32(-3,-7.775) 33(-2.5,-7.775) 34(-2,-7.775) 35(-1.5,-7.775) 36(-1,-7.775) 37(-0.5,-7.775) 38(0,-7.775) 39(0.5,-7.775) 40(1,-7.775) 41(1.5,-7.775) 42(2,-7.775) 43(2.5,-7.775) 44(3,-7.775) 45(3.5,-7.775) 46(4,-7.775) 47(4.5,-7.775) 48(5,-7.775) 49(5.5,-7.775) 50(6,-7.775) 76(6,7.775) 77(5.5,7.775) 78(5,7.775) 79(4.5,7.775) 80(4,7.775) 81(3.5,7.775) 82(3,7.775) 83(2.5,7.775) 84(2,7.775) 85(1.5,7.775) 86(1,7.775) 87(0.5,7.775) 88(0,7.775) 89(-0.5,7.775) 90(-1,7.775) 91(-1.5,7.775) 92(-2,7.775) 93(-2.5,7.775) 94(-3,7.775) 95(-3.5,7.775) 96(-4,7.775) 97(-4.5,7.775) 98(-5,7.775) 99(-5.5,7.775) 100(-6,7.775)
  rect 3.2x3.2 smd: 101(0,0)
IND_1P8X1MM_SM
  rect 0.991x0.711 smd: 1(-0.845,0) 2(0.845,0)
IND_5P2X5P2
  rect 2.007x4.191 smd: 1(-1.903,0) 2(1.903,0)
IND_0402
  round 0.635 smd: 1(-0.508,0) 2(0.508,0)
IND_0402_L
  rrect 0.483x0.635 smd: 1(-0.5,0) 2(0.5,0)
IND_0402_POL
  round 0.635 smd: 1(-0.508,0) 2(0.508,0)
IND_0805
  rect 1.295x1.499 smd: 1(-0.978,0) 2(0.978,0)
IND_1608
  rect 0.61x0.813 smd: 1(-0.7,0) 2(0.7,0)
LED_0603
  rect 0.838x0.787 smd: A(-0.775,0) C(0.775,0)
OSC4_2P1X1P7MM_SM
  rect 0.61x0.787 smd: 1(-0.9,-0.6) 2(0.9,-0.6) 3(0.9,0.6) 4(-0.9,0.6)
PMDU_SOD123
  rect 0.889x1.219 smd: A(1.525,0) C(-1.525,0)
PQFN16_0P4_2P65X1P85
  rect 0.203x0.762 smd: 1(-0.6,-0.724)
  rect 0.203x0.66 smd: 2(-0.2,-0.775) 3(0.2,-0.775) 4(0.6,-0.775) 9(0.6,0.775) 10(0.2,0.775) 11(-0.2,0.775) 12(-0.6,0.775)
  rect 0.66x0.203 smd: 5(1.21,-0.6) 6(1.21,-0.2) 7(1.21,0.2) 8(1.21,0.6) 13(-1.21,0.6) 14(-1.21,0.2) 15(-1.21,-0.2) 16(-1.21,-0.6)
QFN24_0P5_SQ4_EP2P75
  rect 0.61x0.305 smd: 1(-1.9,1.25) 2(-1.9,0.75) 3(-1.9,0.25) 4(-1.9,-0.25) 5(-1.9,-0.75) 6(-1.9,-1.25) 13(1.9,-1.25) 14(1.9,-0.75) 15(1.9,-0.25) 16(1.9,0.25) 17(1.9,0.75) 18(1.9,1.25)
  rect 0.305x0.61 smd: 7(-1.25,-1.9) 8(-0.75,-1.9) 9(-0.25,-1.9) 10(0.25,-1.9) 11(0.75,-1.9) 12(1.25,-1.9) 19(1.25,1.9) 20(0.75,1.9) 21(0.25,1.9) 22(-0.25,1.9) 23(-0.75,1.9) 24(-1.25,1.9)
  rect 2.743x2.743 smd: 25(0,0)
QFN_48_0P5_7X7_5P7EP
  oval 0.864x0.279 smd: 1(-3.463,2.75) 2(-3.463,2.25) 3(-3.463,1.75) 4(-3.463,1.25) 5(-3.463,0.75) 6(-3.463,0.25) 7(-3.463,-0.25) 8(-3.463,-0.75) 9(-3.463,-1.25) 10(-3.463,-1.75) 11(-3.463,-2.25) 12(-3.463,-2.75) 25(3.463,-2.75) 26(3.463,-2.25) 27(3.463,-1.75) 28(3.463,-1.25) 29(3.463,-0.75) 30(3.463,-0.25) 31(3.463,0.25) 32(3.463,0.75) 33(3.463,1.25) 34(3.463,1.75) 35(3.463,2.25) 36(3.463,2.75)
  oval 0.279x0.864 smd: 13(-2.75,-3.463) 14(-2.25,-3.463) 15(-1.75,-3.463) 16(-1.25,-3.463) 17(-0.75,-3.463) 18(-0.25,-3.463) 19(0.25,-3.463) 20(0.75,-3.463) 21(1.25,-3.463) 22(1.75,-3.463) 23(2.25,-3.463) 24(2.75,-3.463) 37(2.75,3.463) 38(2.25,3.463) 39(1.75,3.463) 40(1.25,3.463) 41(0.75,3.463) 42(0.25,3.463) 43(-0.25,3.463) 44(-0.75,3.463) 45(-1.25,3.463) 46(-1.75,3.463) 47(-2.25,3.463) 48(-2.75,3.463)
  rect 5.69x5.69 smd: 49(0,0)
RC0201
  rect 0.47x0.381 smd: 1(-0.343,0) 2(0.343,0)
RC0402_25
  round 0.635 smd: 1(-0.508,0) 2(0.508,0)
RC0603_OV
  oval 0.889x1.143 smd: 1(-0.762,0) 2(0.762,0)
RC0805_OV
  oval 0.889x1.524 smd: 1(-0.965,0) 2(0.965,0)
SC70-5
  rect 0.406x0.813 smd: 1(-0.65,-1.079) 2(0,-1.079) 3(0.65,-1.079) 4(0.65,1.079) 5(-0.65,1.079)
SH0402
  round 0.65 smd: 1(-0.508,0) 2(0.508,0)
SH0603
  rect 0.991x0.813 smd: 1(-0.8,0) 2(0.8,0)
SH_HDR102_2MM_BOTTOM
  rect 1.499x1.499 hole 0.889: 1(0,0)
  round 1.499 hole 0.889: 2(-2,0)
SLP1616P6
  rect 0.305x0.635 smd: 1(-0.5,-0.76) 2(0,-0.76) 3(0.5,-0.76) 4(0.5,0.76) 5(0,0.76) 6(-0.5,0.76)
  rect 1.295x0.457 smd: 7(0,0)
SO8_1P27_4X5
  rect 1.6x0.61 smd: 1(-2.7,1.905) 2(-2.7,0.635) 3(-2.7,-0.635) 4(-2.7,-1.905) 5(2.7,-1.905) 6(2.7,-0.635) 7(2.7,0.635) 8(2.7,1.905)
SOD123LF
  rect 1.219x1.27 smd: A(1.549,0) C(-1.549,0)
SOD123W
  rect 1.219x1.219 smd: A(1.4,0) C(-1.4,0)
SOD523
  rect 0.61x0.813 smd: A(0.85,0) C(-0.85,0)
SOT23-3
  rect 0.762x0.889 smd: 1(-0.95,-1.1) 2(0.95,-1.1) 3(0,1.1)
SOT23_A
  rect 0.787x0.889 smd: 1(-0.94,-1.003) 2(0.94,-1.003) 3(0,1.003)
SOT89-5
  rect 0.559x1.651 smd: 1(-1.5,-1.5) 3(1.5,-1.5)
  custom 0.438x0.438 smd: 2(0,0)
  rect 0.559x1.524 smd: 4(1.5,1.564) 5(-1.5,1.564)
SOT223
  rect 1.194x2.21 smd: 1(-2.3,-3.1) 2(0,-3.1) 3(2.3,-3.1)
  rect 3.734x2.21 smd: 4(0,3.1)
SOT-363_0P65_SMT
  rect 0.762x0.381 smd: 1(-1.085,0.65) 2(-1.085,0) 3(-1.085,-0.65) 4(1.085,-0.65) 5(1.085,0) 6(1.085,0.65)
SSOP8_DCU
  rect 0.279x1.219 smd: 1(-0.75,-1.499) 2(-0.25,-1.499) 3(0.25,-1.499) 4(0.75,-1.499) 5(0.75,1.499) 6(0.25,1.499) 7(-0.25,1.499) 8(-0.75,1.499)
SW2_SPST_4X3_SM
  rect 0.965x1.397 smd: 1(-2.075,0) 2(2.075,0)
  rect 1.143x0.762 smd: G1(-1.575,1.525) G2(-1.575,-1.525) G3(1.575,1.525) G4(1.575,-1.525)
TEST_LOOP
  round 1.524 hole 1.016: 1(0,0)
TESTPOINT_35MIL
  round 0.889 smd: 1(0,0)
TP_2P7X4P7MM
  rect 2.692x4.699 smd: 1(0,0)
TPAD_030
  round 0.762 smd: 1(0,0)
TPAD_040
  round 1.016 smd: 1(0,0)
UDFN6_1X1P5MM
  rect 0.584x0.305 smd: 1(-0.418,0.5)
  rect 0.508x0.305 smd: 2(-0.38,0) 3(-0.38,-0.5) 4(0.38,-0.5) 5(0.38,0) 6(0.38,0.5)
UDFN8_0P5_3X2MM
  oval 0.965x0.279 smd: 1(-1.425,0.75) 2(-1.425,0.25) 3(-1.425,-0.25) 4(-1.425,-0.75) 5(1.425,-0.75) 6(1.425,-0.25) 7(1.425,0.25) 8(1.425,0.75)
  rect 0.203x1.6 smd: 9(0,0)
unnamed#2
  round 1.016 smd: (0,0)
XTAL2_2X1P2_SM
  rect 1.016x1.27 smd: 1(-0.75,0) 2(0.75,0)
XTAL2_3P3X2P6
  rect 1.6x2.718 smd: 1(-1,0) 2(1,0)
XTAL4_1P6X1P2
  rect 0.762x0.61 smd: 1(-0.531,-0.405) 2(0.531,-0.405) 3(0.531,0.405) 4(-0.531,0.405)

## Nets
1V8_DCDC: C5.1 C6.1 JP10.1 L1.2 R89.2
3V3_MIKROE: J1.7 SH12.1
5V_MIKROE: J2.7 SH14.2
GND: BT1.2(-) BT2.2(-) C1.2 C2.2 C5.2 C6.2 C7.2 C8.2 C9.2 C10.2 C11.2 C12.2 C13.2 C14.2 C15.2 C16.2 C17.2 C18.2 C19.2 C20.2 C21.2 C22.2 C23.2 C24.2 C25.2 C26.2 C27.2 C28.2 C29.2 C30.2 C31.2 C32.2 C33.2 C34.2 C35.2 C36.2 C37.2 C38.2 C39.2 C40.2 C41.2 C42.2 C43.2 C44.2 C45.2 C46.2 C47.2 C49.2 C50.2 C51.2 C52.2 C53.2 C54.2 C55.2 C56.2 C57.2 C58.2 C59.2 C60.2 C61.2 C62.2 C63.2 C64.2 C65.2 C66.2 C67.2 C68.2 C69.2 C70.2 C71.2 C72.2 C73.2 C74.2 C75.2 C76.2 C77.2 C78.2 C79.2 C80.2 C81.2 C82.2 C83.2 C84.2 C85.2 C86.2 C87.2 C88.2 C89.2 C90.2 C91.2 C92.2 C93.2 C94.2 C95.2 C97.2 C98.2 C99.2 C100.2 C101.2 C102.2 C103.2 C104.2 C105.2 C106.2 C107.2 C108.2 C109.2 C110.1 C111.2 C112.2 C113.2 D13.A D14.A D15.2 J1.8 J2.8 J3.5 J4.3 J4.5 J4.9 J5.3 J5.5 J7.2 J7.3(GND2) J8.2 J8.3(GND2) J9.2 J9.3 J9.SH1 J9.SH2(SHIELD2) J10.4 JP12.1 JP21.1 JP22.1 L9.2 LED3.C(CATHODE) Q1.2(SOURCE) Q2.2(SOURCE) Q3.2(SOURCE) R28.1 R29.1 R38.1 R41.2 R44.2 R53.2 R66.2 R70.2 R71.2 R74.2 R77.2 R79.2 R80.2 R94.2 R95.2 R96.2 R104.2 R105.2 R106.2 R110.2 SW1.1 SW1.G1 SW1.G2 SW1.G3 SW1.G4 SW2.1 SW2.G1 SW2.G2 SW2.G3 SW2.G4 SW3.1 SW3.G1 SW3.G2 SW3.G3 SW3.G4 SW4.G1 SW4.G2 SW4.G3 SW4.G4 TP15.1 TP16.1 TP17.1 TP18.1 U1.19(VSS_DCDC) U1.49 U2.1 U2.2 U2.3 U2.4 U2.6 U2.7 U2.9 U2.10 U2.12 U2.13 U2.15 U2.20 U2.21 U2.23 U2.24 U2.25 U4.1 U5.4 U5.9 U6.18 U6.19 U6.33 U6.37 U6.46 U6.47 U6.52 U6.99 U6.101 U7.2 U7.3 U8.2(VSS) U9.7 U10.4 U11.6 U12.2 U13.2 U14.2 U15.3 U16.2 U16.5 U16.6 U16.8 U16.17 U17.2 U18.1 U19.2 U19.8 U20.2 U20.5 U21.2 U21.4 Y1.2 Y1.4 Y3.1 Y3.2
P3V3: JP19.3
P3V3_BATT: BT1.1 BT2.1 D2.A
P3V3_LDO: D1.C JP19.1 SH19.2
P5V: C23.1 D4.C D16.C R97.1 SH14.1 TP7.1(PIN1) U4.3
P5V_CAN: C103.1 C105.1 C106.1 C109.1 C111.1 D16.A U17.1 U18.2(VOUT) U18.4 U19.3 U19.5(VIO) U20.1
P12V: D8.A J9.1 J10.3
P12V_VBAT: C107.1 C108.1 D8.C(CATHODE) U18.3
VBAT: C25.1 D2.C JP2.1
VBAT_DCDC/VBAT_PMU: C68.1 C69.1 C72.1 L7.2 U6.49 U6.50 U6.51
VBUS_USB: C81.1 J3.1(VBUS) L8.1 U9.6(VBUS)
VCC_IF_LINK: C85.1 C88.1 C90.1 C91.1 C93.1 J5.1 JP18.2 R43.1 R68.1 R72.1 R75.1 R76.1 SW4.1 U10.8(VCCB) U12.6(VCCB) U13.6(VCCB) U14.6(VCCB) U15.5
VCC_TGMCU: C84.1 C94.1 D12.A JP18.1 R67.2 R86.1 R101.1 SH15.2 U11.14(VCC) U16.1 U16.7 U16.10 U16.15
VDD_ANA: C34.1 JP9.2 U1.29
VDD_CORE: C13.1 C14.1 C16.1 C17.1 TP1.1(PIN1) U1.16 U1.41
VDD_DCDC: C30.1 C31.1 C47.1 R9.1 R24.1 R108.2 U1.21 Y3.4(VCC)
VDD_IC: JP2.2 JP2.3 R107.1
VDD_IO_ABC: C32.1 C33.1 JP8.2 U1.4
VDD_LDO_CORE: C35.1 C36.1 C37.1 JP4.1 U1.15
VDD_MEM: C44.1 JS1.1 R10.1 R11.1 R19.1 R20.1 U5.8
VDD_PA_2G4: C7.1 C18.1 L2.1 R89.1 TP3.1(PIN1) U1.36
VDD_REG: JP3.2 JP7.1 JP8.1 JP9.1 JP10.3
VDD_RF: C40.1 C41.1 R109.2 U1.34
VDD_SWITCH: C26.1 C27.1 JP1.1 U1.6
VOUT_SYS/VDD_SYS: C38.1 C39.1 U1.22
ADC0_A13: R8.2 SH2.2
ADC_IN: J1.1 SH2.1
ANT: L2.2 L3.1 U1.35
ANT_A: E1.2
ANT_B: E2.2
ANT_RF: C1.1 L3.2 L10.1
BOOT_CFG: C113.1 JP16.2 SW4.2(S2)
CAN_DIR: R97.2 U17.5
CAN_HI: J10.1 R99.2 U19.7
CAN_LO: J10.2 R45.1 U19.6
CAN_RX: U17.3 U19.4
CAN_TX: U19.1 U20.3
CS: R11.2 R16.2 R21.2 TP11.1(PIN1) U5.1
DBGIF_DETECT: R81.1 U6.78
DBGIF_ISP0_CTRL: U6.72 U15.2
DBGIF_RESET: U6.90 U14.3
DBGIF_RESET_TXEN: R80.1 U6.71 U14.5
DBGIF_TCK_SWCLK: U6.54 U10.2
DBGIF_TDI: U6.7 U10.3
DBGIF_TDO_SWO: U6.83 U12.3
DBGIF_TMS_SWDIO: U6.81 U13.3
DBGIF_TMS_SWDIO_TXEN: R74.1 U6.66 U13.5
DBGIF_VREF: C82.1 R43.2 R44.1 U6.23
DCDC_LX: L1.1 R1.1 U1.20
EXTAL32K: C50.1 R31.2 Y2.2
EXTAL_32M: R32.2 Y1.3
EXTAL_RF: C48.1 R32.1 U1.33
FL_USB1_DM: R39.2 U6.35
FL_USB1_DP: R40.2 U6.34
FL_USB_5V0: C75.1 C76.1 D4.A L8.2 R37.1 U8.1 U8.4
H/RST: R18.2 R20.2 U5.7
HW_VER_1: R102.1 U6.73
HW_VER_2: R104.1 U6.65
HW_VER_3: R105.1 U6.1
HW_VER_4: R106.1 U6.31
HW_VER_6: JP21.2 Q3.1 U6.56
HW_VER_7: JP22.2 U6.27 U10.5
HW_VER_8: R96.1 U6.55
IF_DETECT: D14.C J5.9 R77.1 R81.2
IF_ISPEN: D13.C J5.7 R83.2
IF_TCK_SWDCLK: D15.5 J5.4 R63.2 R79.1 U11.3
IF_TDI: D15.3 J5.8 R64.2
IF_TDO_SWO: D15.4 J5.6 R69.2 U11.11
IF_TMS_SWDIO: D15.6(K5) J5.2 R73.2 R75.2 U11.15
IF_TRGRST_SWDRST: D15.1 J5.10(B5) R78.2 U11.7
L_R1: LED1.A R22.2
L_Y2: LED2.A R23.2
LED1_R: LED1.C(CATHODE) Q1.3
LED1_R1: Q1.1 R26.2 R28.2
LED2_Y: LED2.C(CATHODE) Q2.3
LED2_Y2: Q2.1 R27.1 R29.2
LED_RST: D3.A R24.2
LLWU/NMI_B: J2.2 SH5.2
LPI2C1_SCL: J2.5 SH11.2
LPI2C1_SDA: J2.6 SH13.2
LPSPI1_PSC0: J1.3 SH4.1
LPSPI1_SCK: J1.4 SH6.1
LPSPI1_SIN: J1.5 SH8.1
LPSPI1_SOUT: J1.6 SH10.1
LPUART0_RX: J2.3 SH7.2
LPUART0_TX: J2.4 SH9.2
MCU_LINK_3V3: C51.1 C52.1 C54.1 C55.1 C56.1 C57.1 C58.1 C59.1 C60.1 C61.1 C62.1 C79.1 C80.1 L4.2 U6.15 U6.25 U6.38 U6.44 U6.63 U6.69 U6.75 U6.84 U6.95 U6.96 U6.100
MCU_LINK_N_16MHZ: C78.1 U6.28 Y4.1
MCU_LINK_P_16MHZ: C77.1 U6.29 Y4.2
MCU_LINK_RST: J4.10(B5) U6.32
MCU_LNK_RX: U6.70 U16.13
MCU_LNK_TX: U6.79 U16.14
MCULINK_VDDA: C63.1 C64.1 L5.2 R33.1 U6.16
MLINK_3V3: C53.1 C83.1 C86.1 C87.1 C89.1 C92.1 C95.1 J4.1 L4.1 L5.1 L7.1 R34.2 R46.1 R47.1 R48.1 R50.1 R102.2 U10.1 U12.1 U13.1 U14.1 U16.16(VCCB)
MLINK_FB: C65.1 C66.1 C67.1 L6.2 U6.39 U6.45
MLINK_LX: L6.1 U6.48
P_LED: JS2.1 R22.1 R23.1 R25.1
P_VDD_SWITCH: JP1.2 JP3.1 L13.2
PIO0_5-ISP_EN: J4.7 R51.2
PIO0_5-ISP_EN-LED_SWD_ACT: D7.C(CATHODE) JP12.2 R48.2 R51.1 U6.88
PIO0_10-SWO: J4.6 R46.2 U6.21
PIO0_11-SWDCLK: J4.4 R53.1 U6.13
PIO0_12-SWDIO: J4.2 R47.2 U6.12
PO_LED: LED3.A R25.2
PTA0/SWD_DIO: U1.8 U11.16
PTA1/SWD_CLK: R66.1 U1.9 U11.4
PTA4/SWO/BOOT_CFG: JP16.1 U1.10 U11.12
PTA16: JP13.3 SH7.1 U1.11
PTA17: JP14.3 SH9.1 U1.12
PTA18: C100.1 R94.1 U1.13 U2.17
PTA19: C101.1 R91.2 U1.14 U2.18
PTA20: C102.1 R95.1 U1.17 U2.19
PTA21: C43.1 R8.1 U1.18
PTB0: R16.1 SH4.2 U1.46
PTB1: R13.1 SH8.2 U1.47
PTB2: R12.1 SH6.2 U1.48
PTB3: R14.1 SH10.2 U1.1
PTB4: JP24.3 R18.1 R21.1 U1.2
PTB5: R15.1 SH11.1 U1.3
PTC0: JP23.3 R26.1 U1.37
PTC1: C45.1 R9.2 SW2.2(S2) TP9.1(PIN1) U1.38
PTC2: C21.1 JP13.1 U1.39
PTC3: C22.1 JP14.1 U1.40
PTC4: R100.2 U1.42
PTC5: R98.2 U1.43
PTC6: R27.2 U1.44
PTC7: C46.1 R17.2 SH5.1 SW3.2(S2) TP12.1(PIN1) U1.45
PTD2: JP23.1 U1.25
PTD2/TMP1_CH0: JP23.2 SH3.1
PTD3: JP24.1 U1.26
PTD3/I2C1_SDA: JP24.2 SH13.1
PTD4_XTAL32K: R30.1 U1.27
PTD5_EXTAL32K: R31.1 U1.28
PWM/TMP1_CH0: J2.1 SH3.2
RESET: J1.2 SH1.1
RF1: R92.1 R110.1 U2.14
RF4: C98.1 R93.1 U2.5
RF_50: C2.1 C3.1 L10.2 U21.1
RF_A: C9.1 L11.1 U2.11
RF_ANT_1: C10.1 E1.1 L11.2
RF_ANT_2: C12.1 E2.1 L12.2
RF_B: C11.1 L12.1 U2.8
RF_SMA_1: C97.1 J7.1 R92.2
RF_SMA_2: C99.1 J8.1 R93.2
RST_TGTMCU_B: JP11.2 JP25.2 SH1.2 SW1.2(S2) U1.23
RST_U11: JP25.1 U11.8
SCK: R10.2 R12.2 TP8.1(PIN1) U5.6
SI: R14.2 TP10.1(PIN1) U5.5
SO: R13.2 TP13.1(PIN1) U5.2
SW_50: C3.2 U2.22 U21.3(OUT)
SWITCH_WAKEUP_B: TP4.1(PIN1) U1.5
USB1_VBUS: R37.2 R41.1 U6.36
V_BRD: C19.1 C20.1 C42.1 C104.1 C112.1 JP2.4(B2) JP19.2 JS1.2 JS2.2 R17.1 R91.1 SH12.2 SH15.1 SH19.1 U2.16(VDD) U17.6(VCCB) U20.6(VCCB)
V_LDO_OUT: C24.1 D1.A U4.2(VOUT) U4.4
V_SEC: JP4.2 JP6.1 JP10.2
VOUT_MLINK: C73.1 C74.1 R34.1 U8.5
VOUT_SWITCH: C28.1 C29.1 JP3.3 U1.7
VREF_MCULINK: C70.1 C71.1 R33.2 R42.2 U6.17 U7.1(CATHODE)
VREF_OUT: C15.1 TP2.1(PIN1) U1.30
WP: R15.2 R19.2 U5.3(W\P\/IO2)
XTAL32K: C49.1 R30.2 Y2.1
XTAL_RF: U1.32 Y1.1
N22669333: R63.1 U10.7
N22669352: R64.1 U10.6
N22669391: R65.1 U11.1
N22669418: JP17.1 R65.2 R67.1 U11.2 U11.5 U11.9
N22669601: R70.1 U12.5
N22669605: R68.2 R69.1 U12.4
N22669808: R72.2 R73.1 U13.4
N22669908: D12.C JP18.3
N22670160: R76.2 R78.1 U14.4
N22670341: R83.1 U15.4(Y)
N22888978: JP17.2 R71.1
N22954457: R84.1 U16.3
N22954468: R85.1 R101.2 U16.4
N22954480: Q3.3 R86.2 U16.9
N23403057: JP7.2 R108.1
N23403396: JP6.2 R109.1
N23407124: D3.C(CATHODE) JP11.1
N23407644: C48.2 Y3.3
N23411769: C8.1 R1.2
N23489789: J3.6 J3.7 J3.8 J3.9 L9.1
N23489809: J3.4 TP21.1(TP) U9.3
N23489851: J3.2 R39.1 U9.1
N23489871: J3.3 R40.1 U9.2
N23559922: R38.2 R42.1 U6.58
N23788677: R98.1 U17.4
N23788861: C110.2 R45.2 R99.1
N23789034: R100.1 U20.4
N23802482: D7.A R50.2
N23938720: JP13.2 R84.2
N23938761: JP14.2 R85.2
N23959568: L13.1 R107.2

Pads without a net: BMP1 1; BMP2 1; BMP3 1; BMP4 1; J4 8; U1 24 31; U6 2 3 4 5 6 8 9 10 11 14 20 22 24 26 30 40 41 42 43 53 57 59 60 61 62 64 67 68 74 76 77 80 82 85 86 87 89 91 92 93 94 97 98; U8 3; U9 4 5; U11 10 13; U15 1; U16 11 12

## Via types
v1: diameter 0.457, hole 0.203, TOP to BOTTOM, 1832 vias
v2: diameter 0.457, hole 0.206, TOP to BOTTOM, 164 vias

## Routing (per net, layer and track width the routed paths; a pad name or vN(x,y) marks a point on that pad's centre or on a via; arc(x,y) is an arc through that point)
1V8_DCDC: length 33.4
  TOP w0.305: R89.2 JP10.1
  L4_INT_2 w0.305: 63.15,22.65 63.15,16.95
  L4_INT_2 w0.381: 63.15,22.65 64.69,24.19 65.43,24.19 66.23,24.98 66.23,26.58 64.9,27.9 64.9,31.28 JP10.1 ; v1(56.62,7.61) v1(56.62,8.37) v1(56.62,9.13) 59.17,9.13 62.79,12.75 62.79,16.59 63.15,16.95
3V3_MIKROE: length 56.5
  L3_INT_1 w0.305: J1.7 21.09,32.84 21.09,35.37 21.75,36.03 39.11,36.03 39.44,35.7 51.06,35.7 51.93,36.56 61.09,36.56 62.03,35.62 68.33,35.62 69.48,34.47 v1(69.48,33)
  BOTTOM w0.305: SH12.1 v1(69.48,33)
5V_MIKROE: length 1.8
  BOTTOM w0.127: J2.7 SH14.2
GND: length 662.8
  TOP w0.254: U2.6 78.65,21.25 ; 78.65,21.25 v2(78.31,21.59) ; 78.65,21.25 U2.7 ; 39.73,5.68 U16.8 ; 39.73,5.68 U16.5 ; 39.73,5.68 40.23,5.18 U16.6 ; 39.73,5.68 U16.17 39.02,5.93 38.23,5.14 U16.2 ; U1.19 61.87,17.24 61.62,17.49 v2(61.62,17.97) ; U2.23 76.32,21.75 v2(76.48,21.59) ; U2.13 78.65,23.75 ; 78.65,23.75 v2(78.29,23.39) ; 78.65,23.75 U2.12 ; v2(76.48,21.59) 76.15,21.25 ; v2(76.48,21.59) 76.65,21.42 U2.2 ; 76.15,21.25 U2.24 ; 76.15,21.25 U2.1 ; U2.20 76.35,23.25 v2(76.48,23.39) ; U6.33 44.1,20 43.61,19.52 v1(43.57,19.52) ; U20.2 U20.5 ; v2(64.53,11.2) 63.83,11.9 61.09,11.9 v2(60.83,12.15) ; U2.3 77.15,21.34 v2(77.4,21.59) 77.65,21.34 U2.4 ; v2(77.4,23.39) 77.65,23.64 U2.15 ; U6.99 C80.2 ; J4.5 J4.3 ; R96.2 R38.1 ; v2(76.48,22.5) 76.23,22.75 U2.21 ; C77.2 R41.2 ; C26.2 C29.2 C28.2
  TOP w0.279: 37.28,20.68 v2(37.28,22.5) ; v2(37.28,22.5) 39.09,22.5 ; v2(37.28,22.5) 35.46,22.5 ; v2(37.28,22.5) 37.28,24.32 ; J4.5 24.52,21.12 ; C58.2 38.83,31.71 ; 67.37,23.75 C18.2 ; C18.2 67.37,24.82 ; C18.2 67.91,24.28 ; 62.53,43.76 SW2.G3 64.11,43.76 ; SW1.G2 65.74,2.28 ; SW1.G2 64.95,1.69 ; SW1.G2 64.16,2.28 ; R110.2 79.17,26.2 ; R110.2 79.7,25.67 ; R110.2 79.17,25.14 ; 39.73,4.07 U16.5 ; 37.76,10.32 C63.2 ; C63.2 37.76,11.39 ; C63.2 37.23,10.86 ; C9.2 88.36,35.33 ; C9.2 87.83,34.8 ; C9.2 88.89,34.8 ; C9.2 88.36,34.26 ; 46.1,23.79 v2(46.54,24.23) ; JP21.1 46.25,38.73 ; JP21.1 46.25,36.78 ; JP21.1 45.27,37.75 ; JP21.1 47.23,37.75 ; C23.2 22.93,37.06 ; C23.2 22.93,35.49 ; C23.2 23.59,36.27 ; J3.5 5.07,12.86 ; C59.2 30.26,32.24 ; C59.2 29.73,31.71 ; C59.2 30.26,31.17 ; 44.16,10.26 R44.2 43.37,10.92 ; 42.21,35.79 R96.2 43,35.13 ; 54.7,25.08 C32.2 55.36,25.86 ; 36.03,7.45 C95.2 ; C95.2 36.56,7.98 ; C95.2 37.09,7.45 ; 47.79,2.81 J5.3 ; U4.1 22.72,43.41 ; U4.1 20.08,43.41 ; U4.1 21.4,44.23 ; U4.1 21.4,42.6 ; v2(51.52,22.56) 51.52,23.35 ; v2(51.52,22.56) 51.52,21.78 ; v2(51.52,22.56) 50.86,22.56 ; 3.44,2.71 LED3.C ; LED3.C 4.05,2.07 ; LED3.C 4.05,3.35 ; LED3.C 4.66,2.71 ; C51.2 27.04,15.58 ; C51.2 26.25,16.25 ; C51.2 25.46,15.58 ; C111.2 18.37,28.9 ; C111.2 17.83,28.36 ; C111.2 17.83,29.43 ; C69.2 45.81,33.45 ; C69.2 45.27,32.92 ; C69.2 45.27,33.98 ; 10.2,14.35 U8.2 11.29,11.81 ; U18.1 17.77,43.85 ; U18.1 17.77,41.21 ; U18.1 18.59,42.53 ; U18.1 16.96,42.53 ; C68.2 46.44,34.85 ; C68.2 45.78,35.63 ; C68.2 45.78,34.06 ; C74.2 17.7,15.99 ; C74.2 15.75,15.99 ; C74.2 16.73,16.65 ; 68.87,16.37 C47.2 68.34,16.91 ; 67.97,18.74 v2(68.57,18.74) 68.57,19.27 ; J10.4 3.81,21.96 ; J10.4 3.81,19.87 ; J10.4 2.77,20.91 ; J10.4 4.85,20.91 ; U7.3 44.68,9.11 ; U7.3 44.68,7.91 ; U7.3 45.35,8.51 ; U7.3 44.02,8.51 ; 41.57,11.34 C71.2 ; C71.2 42.23,12.13 ; C71.2 41.57,12.91 ; 61.21,14.72 C8.2 60.68,14.18 ; 72.69,3.81 TP15.1 ; TP15.1 74.25,6.38 ; TP15.1 74.25,1.24 ; TP15.1 75.82,3.81 ; v2(69.63,17.94) 70.23,17.94 ; 76.15,20.08 U2.1 75.78,20.6 ; 89.98,8.05 C12.2 ; C12.2 90.51,8.58 ; C12.2 90.51,7.51 ; C12.2 91.05,8.05 ; JP12.1 22.43,27.67 ; JP12.1 23.4,26.71 ; JP12.1 21.47,26.71 ; JP12.1 22.43,25.74 ; 54.93,5.34 SW4.G4 56.51,5.34 ; C97.2 79.7,28.72 ; C97.2 79.17,29.25 ; C97.2 79.17,28.18 ; J9.3 11.81,37.54 ; J9.3 7.93,37.54 ; J9.3 9.87,38.48 ; J9.3 9.87,36.6 ; 45.78,31.39 C72.2 ; C72.2 46.44,32.18 ; C72.2 45.78,32.97 ; 65.14,10.7 v2(65.92,10.7) ; v2(65.92,10.7) 65.92,10.03 ; v2(65.92,10.7) 66.71,10.7 ; 87.83,10.2 C11.2 ; C11.2 88.36,9.67 ; C11.2 88.36,10.74 ; C11.2 88.89,10.2 ; 33.66,37.72 C24.2 ; C24.2 34.89,38.63 ; C24.2 33.66,39.55 ; 74.98,21.25 U2.24 75.5,20.88 ; C66.2 47.05,27.81 ; C66.2 46.52,27.27 ; C66.2 47.59,27.27 ; 24.35,16.65 C54.2 25.32,15.99 ; C112.2 20.18,27.88 ; C112.2 19.65,27.35 ; C112.2 19.65,28.42 ; 24.52,23.66 J4.9 23.8,24.39 ; 20.54,12.99 C53.2 19.56,13.65 ; 41.06,10.32 C70.2 ; C70.2 41.06,11.39 ; C70.2 41.6,10.86 ; 49.06,2.81 J5.5 ; 32.78,32.47 U15.3 32.15,32.89 ; 36,10.73 C55.2 ; C55.2 36.54,11.26 ; C55.2 35.47,11.26 ; 74.98,21.75 U2.23 ; 41.2,5.31 U16.8 41.84,5.68 ; 24.89,7.65 J2.8 ; J2.8 25.96,8.72 ; J2.8 24.89,9.79 ; J2.8 23.82,8.72 ; C22.2 61.36,26.86 ; C22.2 61.36,25.79 ; C22.2 60.82,26.33 ; 50.48,9.88 C113.2 ; C113.2 51.01,10.41 ; C113.2 51.55,9.88 ; 59.38,43.76 SW2.G1 60.95,43.76 ; C1.2 69.94,23.27 ; C1.2 69.4,23.8 ; C1.2 68.87,23.27 ; SW4.G3 56.51,2.28 ; SW4.G3 54.93,2.28 ; SW4.G3 55.72,1.69 ; SW4.G1 59.66,2.28 ; SW4.G1 58.87,1.69 ; SW4.G1 58.08,2.28 ; 40.23,4.07 U16.6 ; 9.91,19.69 C75.2 ; C75.2 10.88,20.35 ; C75.2 11.86,19.69 ; 14.82,23.17 C106.2 ; C106.2 14.29,23.71 ; C106.2 15.36,23.71 ; U2.15 77.65,24.92 ; 54.56,21.75 v2(54.56,22.54) ; v2(54.56,22.54) 53.9,22.54 ; v2(54.56,22.54) 54.56,23.32 ; 77.15,20.08 U2.3 ; 76.67,12.02 J8.2 ; J8.2 76.67,14.66 ; J8.2 75.94,13.34 ; R104.2 39.31,33.43 ; R104.2 39.84,32.9 ; R104.2 39.31,32.36 ; 42.35,11.43 C82.2 ; C82.2 43.42,11.43 ; C82.2 42.89,10.89 ; C64.2 37.25,12.91 ; C64.2 37.25,11.34 ; C64.2 36.59,12.13 ; 24.89,30.51 J1.8 ; J1.8 25.96,31.58 ; J1.8 24.89,32.65 ; J1.8 23.82,31.58 ; 16.39,24.33 U17.2 ; 72.36,18.19 v2(72.36,18.71) ; v2(72.36,18.71) 72.97,18.71 ; v2(72.36,18.71) 72.36,19.23 ; 31.39,10.35 TP16.1 ; TP16.1 32.95,12.91 ; TP16.1 34.51,10.35 ; TP16.1 32.95,7.78 ; 78.65,24.92 U2.13 79.02,24.4 ; TP17.1 29.39,35.29 ; TP17.1 24.26,35.29 ; TP17.1 26.82,33.73 ; TP17.1 26.82,36.85 ; 27.55,17 C80.2 28.08,16.47 ; 67.31,24.89 C7.2 ; C7.2 67.75,25.41 ; C7.2 67.31,25.93 ; C98.2 79.7,19.33 ; C98.2 79.17,18.8 ; C98.2 79.17,19.86 ; 63.75,3.81 SW1.1 65.15,3.81 ; 72.27,36.51 TP18.1 ; TP18.1 77.4,36.51 ; TP18.1 74.84,34.95 ; TP18.1 74.84,38.07 ; 71.04,43.76 SW3.G4 72.62,43.76 ; JP22.1 63.75,8.26 ; JP22.1 62.77,9.24 ; JP22.1 62.77,7.28 ; JP22.1 61.8,8.26 ; 28.08,16.14 C62.2 27.55,15.6 ; C14.2 58.59,15.04 ; C14.2 58.59,13.97 ; C14.2 58.06,14.51 ; 5.68,17.05 C81.2 6.21,17.58 ; U20.5 18.09,27.38 ; C99.2 79.17,16.82 ; C99.2 79.17,15.75 ; C99.2 79.7,16.28 ; J7.3 76.67,32.98 ; J7.3 75.94,31.66 ; J7.3 76.67,30.34 ; 58.08,5.34 SW4.G2 59.66,5.34 ; 50.1,23.48 R41.2 50.63,22.94 ; C21.2 64.92,26.33 ; C21.2 64.39,25.79 ; C21.2 64.39,26.86 ; 64.53,10.67 v2(64.53,11.2) 65.06,11.2 ; 79.82,21.25 U2.7 79.3,20.88 ; 2.57,42.7 J9.SH1 4.65,43.64 ; 54.54,21.27 C26.2 55.07,21.8 ; U2.10 79.82,22.75 ; 47.53,27.78 C65.2 49.11,27.78 ; C25.2 38.19,42.05 ; C25.2 37.53,41.27 ; C25.2 38.19,40.48 ; J9.2 9.87,43.68 ; J9.2 9.87,41.8 ; J9.2 7.93,42.74 ; J9.2 11.81,42.74 ; J7.2 79.62,32.98 ; J7.2 79.62,30.34 ; J7.2 80.36,31.66 ; 37.86,4.71 U16.2 38.23,4.07 ; 74.19,40.71 SW3.G1 ; SW3.G1 75.77,40.71 ; SW3.G1 74.98,40.11 ; 79.82,23.75 U2.12 79.3,24.12 ; C76.2 12.79,19.94 ; C76.2 12,19.28 ; C76.2 13.58,19.28 ; C49.2 73.16,14.56 ; C49.2 73.7,14.03 ; C49.2 73.16,13.49 ; C50.2 73.16,16.06 ; C50.2 73.16,14.99 ; C50.2 73.7,15.53 ; 13.39,24.56 C110.1 ; C110.1 14.05,25.35 ; C110.1 13.39,26.13 ; v2(72.36,16.91) 72.36,17.43 ; v2(72.36,16.91) 72.36,16.39 ; v2(72.36,16.91) 72.97,16.91 ; 75.77,43.76 SW3.G2 74.19,43.76 ; C104.2 20.18,25.35 ; 64.95,5.93 SW1.G1 64.16,5.34 ; 74.78,42.23 SW3.1 76.18,42.23 ; 68.1,5.93 SW1.G3 68.89,5.34 ; 28.08,26.55 C60.2 27.55,26.02 ; 71.83,40.11 SW3.G3 ; SW3.G3 71.04,40.71 ; SW3.G3 72.62,40.71 ; 27.55,20.02 C61.2 28.08,20.55 ; 78.65,20.08 U2.6 79.02,20.6 ; 44.22,2.59 C91.2 ; C91.2 44.74,2.14 ; C91.2 45.26,2.59 ; 77.65,20.08 U2.4 ; 54.53,11.93 R66.2 55.07,12.47 ; J9.SH2 2.57,34.68 ; J9.SH2 4.65,33.74 ; J9.SH2 2.57,32.8 ; 74.98,23.25 U2.20 ; 63.32,40.11 SW2.G4 ; SW2.G4 64.11,40.71 ; SW2.G4 62.53,40.71 ; 16.39,27.38 U20.2 ; 58.97,42.23 SW2.1 60.37,42.23 ; 39.99,35.13 R38.1 40.78,35.79 ; R106.2 48.22,15.75 ; R106.2 47.69,16.29 ; R106.2 47.69,15.22 ; R105.2 31.04,12.25 ; R105.2 30.51,11.71 ; R105.2 29.97,12.25 ; 59.38,40.71 SW2.G2 ; SW2.G2 60.95,40.71 ; SW2.G2 60.17,40.11 ; 50.63,16.74 C78.2 50.1,17.27 ; C77.2 50.63,21.91 ; 76.65,20.08 U2.2 ; 35.83,31.71 C52.2 35.29,32.24 ; 61.87,15.89 U1.19 ; 73.99,26.74 C101.2 73.46,26.2 ; C10.2 91.05,36.95 ; C10.2 90.51,37.49 ; C10.2 90.51,36.42 ; C10.2 89.98,36.95 ; 47.69,13.77 C56.2 ; C56.2 47.69,14.84 ; C56.2 48.22,14.31 ; 68.89,2.28 SW1.G4 68.1,1.69 ; 36.03,4.4 C94.2 ; C94.2 37.09,4.4 ; C94.2 36.56,3.87 ; C2.2 72.45,23.8 ; C2.2 71.92,23.27 ; C2.2 72.99,23.27 ; J4.3 24.52,19.85 ; 42.48,6.96 U7.2 ; U7.2 43.15,7.56 ; U7.2 41.82,7.56 ; U7.2 42.48,8.16 ; 55.58,23.27 C33.2 55.05,23.81 ; 58.09,14.06 C13.2 57.43,13.27 ; v2(17.83,25.85) 17.83,26.38 ; 67.02,43.25 C45.2 66.48,43.78 ; 15.61,15.58 C73.2 14.82,16.25 ; J8.3 80.36,13.34 ; J8.3 79.62,12.02 ; J8.3 79.62,14.66 ; 74.98,22.75 U2.21 ; U2.9 79.82,22.25 ; 68.13,43.25 C46.2 68.67,43.78 ; 54.54,20.25 C29.2 ; 46.1,23.65 v2(46.54,23.21)
  TOP w0.305: v2(78.29,23.39) v2(77.4,22.5)
  L2_GND_1 w0.254: J5.5 J5.3
  L2_GND_1 w0.279: 45.3,37.75 JP21.1 ; JP21.1 46.25,38.71 ; JP21.1 46.25,36.8 ; JP21.1 47.21,37.75 ; 47.79,2.84 J5.3 ; J1.8 24.89,32.62 ; J1.8 24.89,30.54 ; J1.8 23.85,31.58 ; J1.8 25.93,31.58 ; 9.87,41.83 J9.2 ; J9.2 11.79,42.74 ; J9.2 7.95,42.74 ; J9.2 9.87,43.66 ; 62.77,7.31 JP22.1 ; JP22.1 61.82,8.26 ; JP22.1 62.77,9.22 ; JP22.1 63.73,8.26 ; 23.8,24.36 J4.9 24.5,23.66 ; 24.89,7.68 J2.8 ; J2.8 23.85,8.72 ; J2.8 25.93,8.72 ; J2.8 24.89,9.76 ; J10.4 3.81,21.93 ; J10.4 2.79,20.91 ; J10.4 4.83,20.91 ; J10.4 3.81,19.9 ; 2.57,32.83 J9.SH2 ; J9.SH2 2.57,34.66 ; J9.SH2 4.63,33.74 ; 22.43,25.77 JP12.1 ; JP12.1 23.37,26.71 ; JP12.1 21.49,26.71 ; JP12.1 22.43,27.65 ; 9.87,36.63 J9.3 ; J9.3 9.87,38.46 ; J9.3 7.95,37.54 ; J9.3 11.79,37.54 ; 4.63,43.64 J9.SH1 2.57,42.73 ; J4.3 24.5,19.85 ; 49.06,2.84 J5.5 ; J4.5 24.5,21.12
  L3_INT_1 w0.279: 2.57,32.74 J9.SH2 ; J9.SH2 4.72,33.74 ; J9.SH2 2.57,34.75 ; 24.89,30.45 J1.8 ; J1.8 23.76,31.58 ; J1.8 26.02,31.58 ; JP21.1 47.3,37.75 ; JP21.1 45.21,37.75 ; JP21.1 46.25,38.8 ; J9.3 11.88,37.54 ; J9.3 7.86,37.54 ; J9.3 9.87,36.54 ; J9.3 9.87,38.55 ; J9.2 9.87,43.75 ; J9.2 11.88,42.74 ; J9.2 9.87,41.74 ; J9.2 7.86,42.74 ; 23.76,8.72 J2.8 ; J2.8 24.89,7.59 ; J2.8 26.02,8.72 ; J2.8 24.89,9.85 ; J10.4 4.92,20.91 ; J10.4 2.7,20.91 ; J10.4 3.81,19.81 ; J10.4 3.81,22.02 ; 4.72,43.64 J9.SH1 2.57,42.64 ; JP12.1 23.46,26.71 ; JP12.1 22.43,25.68 ; JP12.1 21.4,26.71 ; JP22.1 63.82,8.26 ; JP22.1 62.77,9.31 ; JP22.1 61.73,8.26 ; JP22.1 62.77,7.22
  L4_INT_2 w0.279: 62.77,7.28 JP22.1 ; JP22.1 62.77,9.24 ; JP22.1 61.8,8.26 ; JP22.1 63.75,8.26 ; 2.57,32.8 J9.SH2 2.57,34.68 ; 9.87,41.8 J9.2 ; J9.2 7.93,42.74 ; J9.2 11.81,42.74 ; J9.2 9.87,43.68 ; 4.65,43.64 J9.SH1 2.57,42.7 ; 7.93,37.54 J9.3 ; J9.3 9.87,38.48 ; J9.3 11.81,37.54 ; J9.3 9.87,36.6 ; 45.27,37.75 JP21.1 ; JP21.1 47.23,37.75 ; JP21.1 46.25,36.78 ; JP21.1 46.25,38.73 ; 22.43,25.74 JP12.1 ; JP12.1 22.43,27.67 ; JP12.1 21.47,26.71 ; 23.82,8.72 J2.8 ; J2.8 24.89,9.79 ; J2.8 25.96,8.72 ; J2.8 24.89,7.65 ; 2.77,20.91 J10.4 ; J10.4 3.81,19.87 ; J10.4 4.85,20.91 ; J1.8 25.96,31.58 ; J1.8 24.89,30.51 ; J1.8 24.89,32.65 ; J4.9 23.8,24.39
  L5_GND_2 w0.279: J10.4 3.81,21.93 ; J10.4 2.79,20.91 ; J10.4 4.83,20.91 ; J10.4 3.81,19.9 ; 21.49,26.71 JP12.1 ; JP12.1 23.37,26.71 ; JP12.1 22.43,25.77 ; JP12.1 22.43,27.65 ; 24.5,23.66 J4.9 23.8,24.36 ; 46.25,36.8 JP21.1 ; JP21.1 47.21,37.75 ; JP21.1 46.25,38.71 ; JP21.1 45.3,37.75 ; 2.57,42.73 J9.SH1 4.63,43.64 ; J4.3 24.5,19.85 ; J2.8 25.93,8.72 ; J2.8 24.89,9.76 ; J2.8 23.85,8.72 ; J2.8 24.89,7.68 ; 9.87,41.83 J9.2 ; J9.2 9.87,43.66 ; J9.2 7.95,42.74 ; J9.2 11.79,42.74 ; 47.79,2.84 J5.3 ; 61.82,8.26 JP22.1 ; JP22.1 62.77,7.31 ; JP22.1 62.77,9.22 ; JP22.1 63.73,8.26 ; J9.3 9.87,38.46 ; J9.3 7.95,37.54 ; J9.3 11.79,37.54 ; J9.3 9.87,36.63 ; J4.5 24.5,21.12 ; 2.57,32.83 J9.SH2 ; J9.SH2 2.57,34.66 ; J9.SH2 4.63,33.74 ; J1.8 25.93,31.58 ; J1.8 24.89,30.54 ; J1.8 23.85,31.58 ; J1.8 24.89,32.62 ; 49.06,2.84 J5.5
  BOTTOM w0.254: v2(57.92,16.52) v2(56.4,16.52) ; C15.2 C40.2 ; v2(71.96,26.2) v2(71.96,27.22) v2(72.97,27.22) v2(72.97,26.2) v2(71.96,26.2)
  BOTTOM w0.279: C41.2 68.77,33.56 ; C41.2 68.11,34.54 ; C41.2 68.11,32.58 ; 47.71,9.51 D15.2 46.51,9.51 ; C109.2 18.58,40.36 ; C109.2 17.66,39.12 ; C109.2 19.49,39.12 ; C107.2 15.36,38.72 ; C107.2 14.7,39.51 ; C107.2 14.7,37.93 ; 20.11,19.32 R53.2 ; R53.2 19.58,19.85 ; R53.2 20.11,20.38 ; 64.22,1.54 U10.4 ; U10.4 63.87,2.36 ; U10.4 64.22,3.19 ; C34.2 67.4,18.35 ; C34.2 68.06,17.56 ; C34.2 67.4,16.77 ; D13.A 46.76,2.2 ; D13.A 46.76,0.96 ; D13.A 46.24,1.58 ; D13.A 47.28,1.58 ; JP21.1 47.23,37.75 ; JP21.1 45.27,37.75 ; JP21.1 46.25,36.78 ; JP21.1 46.25,38.73 ; 75.01,27.83 C20.2 75.46,27.31 ; 60.23,0.93 R80.2 ; 24.89,30.51 J1.8 ; J1.8 25.96,31.58 ; J1.8 24.89,32.65 ; J1.8 23.82,31.58 ; 58.03,6.94 C92.2 ; C92.2 58.57,6.4 ; C92.2 58.57,7.47 ; R71.2 50.38,13.8 ; R71.2 49.85,14.33 ; R71.2 49.85,13.27 ; 7.93,37.54 J9.3 ; J9.3 9.87,36.6 ; J9.3 9.87,38.48 ; 21.47,26.71 JP12.1 ; JP12.1 23.4,26.71 ; JP12.1 22.43,25.74 ; JP12.1 22.43,27.67 ; 65.34,20.77 C15.2 64.27,20.77 ; 23.8,24.39 J4.9 24.52,23.66 ; JP22.1 63.75,8.26 ; JP22.1 61.8,8.26 ; JP22.1 62.77,9.24 ; 3.67,13.37 U9.7 ; 2.57,42.7 J9.SH1 4.65,43.64 ; Q2.2 5.18,3.96 ; Q2.2 5.79,3.3 ; Q2.2 4.57,3.3 ; Q2.2 5.18,2.64 ; 8.99,2.64 Q1.2 ; Q1.2 9.6,3.3 ; Q1.2 8.99,3.96 ; Q1.2 8.38,3.3 ; R77.2 53.05,5.85 ; R77.2 53.58,5.32 ; R77.2 52.51,5.32 ; J9.SH2 2.57,34.68 ; J9.SH2 2.57,32.8 ; J9.SH2 4.65,33.74 ; D14.A 50.42,1.58 ; D14.A 49.38,1.58 ; D14.A 49.9,0.96 ; D14.A 49.9,2.2 ; v2(72.97,26.2) 73.51,26.2 ; 4.85,4.57 R29.1 4.32,4.03 ; C108.2 14.72,40.12 ; C108.2 14.19,40.65 ; C108.2 14.19,39.58 ; 65.77,37.14 C44.2 66.3,36.61 ; C43.2 62.92,16.54 ; C43.2 62.39,16 ; C43.2 62.39,17.07 ; J4.5 24.52,21.12 ; 59.22,0.93 C93.2 58.68,1.46 ; 3.81,19.87 J10.4 ; J10.4 2.77,20.91 ; J10.4 3.81,21.96 ; J10.4 4.85,20.91 ; 56.4,17.18 v2(56.4,16.52) 55.61,16.52 ; Q3.2 45.5,9.12 ; Q3.2 44.89,8.46 ; Q3.2 45.5,7.8 ; Q3.2 46.11,8.46 ; U5.9 64.88,40.94 ; U5.9 65.2,39.92 ; U5.9 64.56,39.92 ; 55.66,5.2 U12.2 ; 63.39,22.73 C16.2 62.85,23.26 ; J2.8 24.89,9.79 ; J2.8 24.89,7.65 ; J2.8 25.96,8.72 ; J2.8 23.82,8.72 ; L9.2 1.5,14.13 ; L9.2 2.12,13.61 ; L9.2 0.88,13.61 ; L9.2 1.5,13.09 ; 8.89,21.05 C105.2 ; C105.2 9.42,20.52 ; C105.2 9.96,21.05 ; 70.25,7.47 C89.2 70.79,6.94 ; 54.11,1.46 C88.2 54.65,0.93 ; 7.93,42.74 J9.2 ; J9.2 9.87,43.68 ; J9.2 11.81,42.74 ; J9.2 9.87,41.8 ; 8.41,27.26 U19.8 ; U19.8 10.44,27.26 ; U19.8 9.42,26.74 ; 8.66,4.57 R28.1 8.13,4.03 ; 64.81,22.28 C40.2 64.27,21.75 ; 48.8,6.71 R79.2 48.8,5.65 ; 60.89,13.79 C35.2 61.42,14.33 ; C42.2 69.24,35.68 ; C42.2 68.8,35.16 ; C42.2 69.24,34.64 ; J4.3 24.52,19.85 ; 71.42,27.22 v2(71.96,27.22) ; v2(72.97,27.22) 73.51,27.22 ; 65.3,12.93 C38.2 64.64,12.14 ; 67.4,3.38 C86.2 66.33,3.38 ; 75.72,26.28 C19.2 ; C19.2 75.72,27.09 ; C19.2 75.27,26.69 ; BT1.2 38.8,6.79 ; BT1.2 40.77,5.28 ; BT1.2 38.8,3.77 ; 13.81,25.99 U19.2 ; U19.2 15.84,25.99 ; U19.2 14.82,26.51 ; U19.2 14.82,25.47 ; 55.66,0.93 R70.2 ; 47.79,2.81 J5.3 ; 60.23,5.2 U14.2 60.23,6.39 ; 52.58,5.77 C87.2 ; C87.2 52.04,6.31 ; C87.2 52.58,6.84 ; 37.28,13.68 BT2.2 ; BT2.2 38.8,15.4 ; BT2.2 40.31,13.68 ; BT2.2 38.8,11.97 ; 69.89,6.39 U13.2 69.89,5.2 ; 64.64,15.24 C39.2 65.3,14.45 ; C83.2 25.19,20.13 ; C83.2 25.73,19.6 ; C83.2 24.66,19.6 ; 58.47,13.01 C84.2 57.93,13.54 ; 52.92,12.61 U11.6 ; U5.4 63.45,41.03 ; U5.4 64.15,40.67 ; U5.4 62.75,40.67 ; 71.42,26.2 v2(71.96,26.2) ; 69.89,0.93 R74.2 ; 67.4,4.34 C85.2 66.33,4.34 ; v2(57.92,16.52) 57.92,17.18 ; 64.94,23.26 C17.2 64.4,22.73 ; 68.34,1.46 C90.2 68.87,0.93
  BOTTOM w0.305: C38.2 C39.2
  vias: v1(2.06,41.43) v1(2.06,40.16) v1(2.06,38.89) v1(2.06,35.08) v1(2.06,32.54) v1(2.06,31.27) v1(2.06,30) v1(2.06,28.73) v1(2.06,27.46) v1(2.06,26.19) v1(2.06,24.92) v1(2.06,22.38) v1(2.06,21.11) v1(2.06,19.84) v1(2.06,8.41) v1(2.06,7.14) v1(2.06,5.87) v1(2.06,4.6) v1(2.06,3.33) v1(2.06,2.06) v1(3.33,41.43) v1(3.33,40.16) v1(3.33,35.08) v1(3.33,32.54) v1(3.33,31.27) v1(3.33,30) v1(3.33,18.57) v1(3.33,9.68) v1(3.33,8.41) v1(3.33,7.14) v1(4.33,31.91) v1(4.33,30.54) v1(4.6,42.7) v1(4.6,41.43) v1(4.6,40.16) v1(4.6,35.08) v1(4.6,19.84) v1(4.6,18.57) v1(4.6,9.68) v1(5.04,21.47) v1(5.52,19.24) v1(5.62,20.46) v1(5.87,43.97) v1(5.87,42.7) v1(5.87,41.43) v1(5.87,40.16) v1(5.87,38.89) v1(5.87,37.62) v1(5.87,36.35) v1(5.87,9.68) v1(5.87,8.41) v1(5.87,7.14) v1(6.08,10.65) v1(6.13,3.49) v1(6.1,1.1) v1(6.31,11.87) v1(6.54,22.21) v1(7.02,10.17) v1(7.14,43.97) v1(7.14,42.7) v1(7.14,41.43) v1(7.14,40.16) v1(7.14,38.89) v1(7.14,37.62) v1(7.14,36.35) v1(7.14,27.46) v1(7.14,26.19) v1(7.15,24.54) v1(7.14,23.65) v1(7.15,20.86) v1(7.73,26.83) v1(7.83,24.04) v1(8.41,43.97) v1(8.41,41.43) v1(8.41,40.16) v1(8.41,38.89) v1(8.41,36.35) v1(8.41,31.27) v1(8.41,28.73) v1(9,7.65) v1(9.68,43.97) v1(9.68,41.43) v1(9.68,40.16) v1(9.68,38.89) v1(9.68,36.35) v1(9.68,4.6) v1(9.84,2.45) v1(10.04,20.46) v1(9.99,6.18) v1(10.09,3.34) v1(10.55,11.59) v1(10.5,10.63) v1(10.7,25.36) v1(10.95,43.97) v1(10.95,41.43) v1(10.95,40.16) v1(10.95,38.89) v1(10.95,36.35) v1(10.95,31.27) v1(10.95,28.73) v1(10.93,22.72) v1(10.95,9.68) v1(10.95,8.41) v1(10.95,2.06) v1(11.01,7.6) v1(12.22,43.97) v1(12.22,27.46) v1(12.22,23.65) v1(12.17,21.67) v1(12.63,26.27) v1(12.68,24.42) v1(13.29,22.97) v1(13.49,32.54) v1(13.49,31.27) v1(13.49,28.73) v1(13.49,27.46) v1(13.47,19.97) v1(13.49,13.49) v1(13.57,26.63) v1(14.08,20.35) v1(14.16,19.13) v1(16.03,40.16) v1(16.03,38.89) v1(16.03,19.84) v1(16.03,18.57) v1(16.04,10.57) v1(16.03,9.68) v1(16.03,8.41) v1(16.11,7.63) v1(17.18,23.05) v1(17.3,40.16) v1(17.3,38.89) v1(17.3,19.84) v1(17.3,18.57) v1(18.14,4.99) v1(18.57,5.87) v1(18.57,2.06) v1(19.84,43.97) v1(19.84,12.22) v1(21.75,30.39) v1(22.38,7.14) v1(23.53,37.07) v1(23.65,43.97) v1(23.65,38.89) v1(23.66,35.31) v1(23.65,33.81) v1(23.6,9.38) v1(23.65,8.41) v1(23.65,7.14) v1(23.65,5.87) v1(23.65,4.6) v1(23.65,3.33) v1(23.65,2.06) v1(24.34,30.36) v1(24.92,43.97) v1(24.92,38.89) v1(24.92,37.62) v1(24.92,7.14) v1(24.92,5.87) v1(24.92,4.6) v1(24.92,3.33) v1(24.92,2.06) v1(25.74,26.81) v1(26.02,32.37) v1(26.19,43.97) v1(26.19,37.62) v1(26.19,27.46) v1(26.19,26.19) v1(26.19,21.11) v1(26.19,18.57) v1(26.19,10.95) v1(26.19,9.68) v1(26.19,8.41) v1(26.19,7.14) v1(26.19,5.87) v1(26.19,4.6) v1(26.19,3.33) v1(26.19,2.06) v1(26.55,23.76) v1(26.78,31.73) v1(27.06,25.1) v1(27.34,32.37) v1(27.46,43.97) v1(27.46,21.11) v1(27.46,12.22) v1(27.46,10.95) v1(27.46,9.68) v1(27.46,8.41) v1(27.46,7.14) v1(27.46,5.87) v1(27.46,4.6) v1(27.46,3.33) v1(27.46,2.06) v1(27.9,31.73) v1(28.56,29.22) v1(28.61,32.32) v1(28.73,10.95) v1(29.17,31.71) v1(29.17,9.1) v1(29.17,8.19) v1(29.17,7.2) v1(29.55,29.27) v1(30,7.14) v1(30,3.33) v1(30,2.06) v1(30,1.09) v1(30.13,10.4) v1(30.21,36.84) v1(30.87,28.08) v1(31.27,34.15) v1(31.27,28.73) v1(31.27,26.19) v1(31.27,5.87) v1(31.27,3.33) v1(31.27,2.06) v1(31.27,1.09) v1(31.38,36.84) v1(31.52,35.09) v1(31.61,25.1) v1(31.86,4.3) v1(31.96,28.15) v1(32.14,6.99) v1(32.06,5.32) v1(32.42,40.24) v1(32.54,41.43) v1(32.54,28.73) v1(32.54,26.19) v1(32.54,24.92) v1(32.54,1.09) v1(32.79,35.11) v1(33.23,17.48) v1(33.23,7.43) v1(33.23,5.47) v1(33.21,3.97) v1(33.81,3.33) v1(33.81,2.06) v1(33.81,1.09) v1(34.23,26.56) v1(34.23,25.55) v1(34.23,23.52) v1(34.23,22.5) v1(34.23,21.48) v1(34.35,39.94) v1(34.55,29.12) v1(34.5,7.48) v1(34.53,5.16) v1(34.68,37.4) v1(34.75,11.46) v1(34.75,9.41) v1(35.01,3.77) v1(35.08,24.92) v1(35.08,2.06) v1(35.08,1.09) v1(35.24,26.56) v1(35.24,25.55) v1(35.24,23.52) v1(35.24,22.5) v1(35.24,21.48) v1(35.24,19.45) v1(35.29,28.38) v1(35.75,7.81) v1(35.87,4.86) v1(36,17.76) v1(36.26,26.56) v1(36.26,25.55) v1(36.26,19.45) v1(36.26,18.44) v1(36.35,24.92) v1(36.35,2.06) v1(36.54,3.01) v1(36.89,11.18) v1(37.28,26.56) v1(37.28,25.55) v1(37.27,24.95) v1(37.28,19.45) v1(37.28,18.44) v1(37.28,17.42) v1(37.53,7.5) v1(37.88,3.28) v1(38.29,26.56) v1(38.29,25.55) v1(38.29,19.45) v1(38.29,18.44) v1(38.29,17.42) v1(38.29,15.93) v1(39.31,26.56) v1(39.31,25.55) v1(39.31,23.52) v1(39.31,22.5) v1(39.28,21.47) v1(39.31,19.45) v1(39.31,18.44) v1(39.31,17.42) v1(40.03,15.88) v1(40.16,3.33) v1(40.32,26.56) v1(40.32,25.55) v1(40.32,23.52) v1(40.32,22.5) v1(40.32,19.45) v1(40.32,18.44) v1(40.32,17.42) v1(41.31,27.06) v1(41.34,23.52) v1(41.34,22.5) v1(41.34,19.45) v1(41.34,18.44) v1(41.34,17.42) v1(41.43,26.19) v1(41.41,25.21) v1(41.38,21.52) v1(41.71,13.17) v1(41.71,3.89) v1(41.77,28.99) v1(41.97,11.21) v1(42.1,26.02) v1(42.1,6.71) v1(42.2,19.44) v1(42.2,18.45) v1(42.5,3.82) v1(42.66,29.02) v1(42.76,27.95) v1(43.54,13.19) v1(43.75,27.08) v1(43.72,6.64) v1(43.72,5.7) v1(44.69,9.51) v1(45.45,5.11) v1(45.52,6.03) v1(45.47,4.33) v1(45.57,1.53) v1(46.06,9.51) v1(46.26,26.98) v1(46.26,13.39) v1(46.97,5.75) v1(47.12,10.9) v1(47.35,28.18) v1(47.65,1.53) v1(48.04,16.47) v1(48.24,22.21) v1(48.27,25.33) v1(48.42,9.94) v1(48.42,5.52) v1(49.69,5.47) v1(50.85,1.53) v1(50.96,30.82) v1(51.01,21.57) v1(50.99,15.88) v1(50.99,2.8) v1(51.14,19.11) v1(51.14,18.42) v1(51.14,11.03) v1(51.19,19.92) v1(51.34,27.11) v1(51.39,5.7) v1(51.56,12.46) v1(51.67,11.54) v1(51.77,10.52) v1(51.77,9.48) v1(52.41,33.56) v1(52.53,3.03) v1(52.59,27.08) v1(52.86,1.46) v1(53.58,35.82) v1(53.65,34.73) v1(53.65,33.59) v1(53.62,1.46) v1(53.95,17.97) v1(53.92,5.5) v1(54.13,3.03) v1(54.49,33.61) v1(54.62,23.76) v1(55.52,17.97) v1(56.14,34.6) v1(56.19,35.82) v1(56.94,14.24) v1(56.91,3.87) v1(57.11,13.69) v1(57.23,29.12) v1(57.34,31.73) v1(57.48,1.46) v1(57.67,32.39) v1(58.5,28.58) v1(58.91,12.25) v1(59.85,12.25) v1(60.26,38.44) v1(60.26,34.73) v1(60.23,5) v1(60.28,33.66) v1(60.49,13.29) v1(60.79,42.76) v1(61.15,30.08) v1(61.25,38.46) v1(61.32,7.65) v1(61.48,31.02) v1(61.65,42.88) v1(61.65,14.97) v1(62.27,1.49) v1(62.52,6.33) v1(62.62,42.71) v1(62.9,1.49) v1(63.02,9.68) v1(63.49,4.05) v1(63.54,1.49) v1(63.64,2.45) v1(64.14,8.8) v1(64.17,7.55) v1(64.29,9.68) v1(64.37,40.29) v1(64.37,39.51) v1(64.65,43.21) v1(64.91,41.61) v1(65.29,15.71) v1(65.39,40.39) v1(65.39,39.51) v1(65.67,41.36) v1(66.45,28.71) v1(66.5,31.1) v1(66.5,8.14) v1(66.48,0.8) v1(66.85,15.33) v1(66.96,21.54) v1(67.06,7.53) v1(67.24,43.24) v1(67.17,22.96) v1(67.32,0.8) v1(67.37,41.74) v1(67.37,34.81) v1(67.39,18.88) v1(67.45,3.89) v1(67.62,42.5) v1(67.6,21.54) v1(67.67,19.82) v1(67.75,1.35) v1(67.8,22.96) v1(67.9,43.21) v1(67.88,26.63) v1(68,25.89) v1(67.98,23.76) v1(68.11,34.93) v1(68.13,0.8) v1(68.23,21.54) v1(68.41,24.29) v1(68.44,22.96) v1(68.43,19.82) v1(68.74,23.76) v1(68.68,13.55) v1(68.94,32.27) v1(68.87,21.54) v1(69.15,37.88) v1(69.17,41.69) v1(69.22,36.28) v1(69.37,24.92) v1(69.4,24.27) v1(69.42,12.76) v1(69.38,0.8) v1(69.5,21.54) v1(69.49,10.95) v1(69.57,13.55) v1(69.93,36.91) v1(70.14,23.83) v1(70.14,21.54) v1(70.29,22.96) v1(70.42,25.87) v1(70.41,20.02) v1(70.38,19.29) v1(70.54,24.57) v1(70.51,0.81) v1(70.65,44.15) v1(70.7,32.39) v1(70.77,21.54) v1(70.79,17.76) v1(70.92,23.78) v1(70.93,22.96) v1(71.33,25.74) v1(71.36,5.52) v1(71.38,24.44) v1(71.41,21.54) v1(71.5,17.76) v1(71.66,37.57) v1(71.66,36.51) v1(71.56,22.96) v1(71.74,35.34) v1(71.69,23.76) v1(71.78,0.81) v1(71.92,20.65) v1(71.92,19.89) v1(71.91,4.6) v1(72.04,21.54) v1(72.14,5.44) v1(72.3,39.78) v1(72.45,24.24) v1(72.42,0.81) v1(72.63,32.11) v1(72.68,31.02) v1(72.68,21.54) v1(72.68,20.65) v1(72.68,19.89) v1(72.77,17.79) v1(73.05,0.81) v1(73.18,42.7) v1(73.18,41.43) v1(73.18,33.81) v1(73.18,23.65) v1(73.31,21.54) v1(73.42,43.77) v1(73.44,20.65) v1(73.44,19.89) v1(73.44,19.13) v1(73.44,18.36) v1(73.44,17.6) v1(73.47,22.96) v1(73.62,40.7) v1(73.69,0.81) v1(73.82,23.6) v1(73.95,21.54) v1(74.1,22.96) v1(74.2,20.65) v1(74.2,19.89) v1(74.2,19.13) v1(74.2,18.36) v1(74.2,17.6) v1(74.31,42.22) v1(74.34,34.69) v1(74.34,34.06) v1(74.34,33.42) v1(74.34,32.79) v1(74.34,32.15) v1(74.34,31.52) v1(74.34,30.88) v1(74.34,30.25) v1(74.34,29.61) v1(74.33,15.4) v1(74.33,14.77) v1(74.33,14.13) v1(74.33,13.5) v1(74.32,0.81) v1(74.56,27.82) v1(74.58,21.54) v1(74.74,22.96) v1(74.81,38.59) v1(74.96,0.81) v1(74.99,39.56) v1(74.97,34.69) v1(74.97,34.06) v1(74.97,33.42) v1(74.97,32.79) v1(74.97,32.15) v1(74.97,31.52) v1(74.97,30.88) v1(74.97,30.25) v1(74.97,29.61) v1(75.04,27.03) v1(74.97,20.65) v1(74.97,19.89) v1(74.97,19.13) v1(74.97,18.36) v1(74.97,15.39) v1(74.97,14.75) v1(74.97,14.12) v1(74.97,13.48) v1(74.97,12.85) v1(74.97,12.21) v1(74.97,10.31) v1(74.97,9.67) v1(74.97,9.04) v1(75.61,34.69) v1(75.61,34.06) v1(75.61,33.42) v1(75.61,32.79) v1(75.61,32.15) v1(75.61,31.52) v1(75.61,30.88) v1(75.61,30.25) v1(75.61,29.61) v1(75.61,15.39) v1(75.61,14.75) v1(75.61,14.12) v1(75.61,13.48) v1(75.61,12.85) v1(75.61,12.21) v1(75.61,11.58) v1(75.61,10.94) v1(75.61,10.31) v1(75.61,9.67) v1(75.61,9.04) v1(75.59,0.81) v1(75.94,19.84) v1(75.94,19.2) v1(75.94,18.57) v1(75.94,17.93) v1(76.23,44.19) v1(76.23,43.56) v1(76.24,34.69) v1(76.24,34.06) v1(76.24,33.42) v1(76.24,29.89) v1(76.24,15.11) v1(76.24,11.58) v1(76.24,10.94) v1(76.24,10.31) v1(76.24,9.67) v1(76.24,9.04) v1(76.23,3.32) v1(76.23,2.71) v1(76.23,2.08) v1(76.23,1.44) v1(76.23,0.81) v1(76.44,40.67) v1(76.57,19.84) v1(76.57,19.2) v1(76.57,18.57) v1(76.57,17.93) v1(76.57,17.3) v1(76.57,16.66) v1(76.57,16.03) v1(76.86,44.19) v1(76.86,43.56) v1(76.86,42.92) v1(76.86,42.29) v1(76.86,41.68) v1(76.88,34.69) v1(76.88,34.06) v1(76.88,33.42) v1(76.88,29.89) v1(76.88,15.11) v1(76.88,11.58) v1(76.88,10.94) v1(76.88,10.31) v1(76.88,9.67) v1(76.88,9.04) v1(76.86,3.32) v1(76.86,2.71) v1(76.86,2.08) v1(76.86,1.44) v1(76.86,0.81) v1(77.21,28.97) v1(77.21,28.34) v1(77.21,27.7) v1(77.21,27.07) v1(77.21,26.43) v1(77.21,25.8) v1(77.21,19.84) v1(77.21,19.2) v1(77.21,18.57) v1(77.21,17.93) v1(77.21,17.3) v1(77.21,16.66) v1(77.21,16.03) v1(77.5,44.19) v1(77.5,43.56) v1(77.5,42.92) v1(77.5,42.29) v1(77.5,41.68) v1(77.51,34.69) v1(77.51,34.06) v1(77.51,33.42) v1(77.51,11.58) v1(77.51,10.94) v1(77.51,10.31) v1(77.51,9.67) v1(77.51,9.04) v1(77.5,3.32) v1(77.5,2.71) v1(77.5,2.08) v1(77.5,1.44) v1(77.5,0.81) v1(78.13,44.19) v1(78.13,43.56) v1(78.13,42.92) v1(78.13,42.29) v1(78.13,41.68) v1(78.15,35.96) v1(78.15,35.33) v1(78.15,34.69) v1(78.15,34.06) v1(78.15,33.42) v1(78.15,11.58) v1(78.15,10.94) v1(78.15,10.31) v1(78.15,9.67) v1(78.15,9.04) v1(78.13,3.32) v1(78.13,2.71) v1(78.13,2.08) v1(78.13,1.44) v1(78.13,0.81) v1(78.77,44.19) v1(78.77,43.56) v1(78.77,42.92) v1(78.77,42.29) v1(78.77,41.68) v1(78.78,35.96) v1(78.78,35.33) v1(78.78,34.69) v1(78.78,34.06) v1(78.78,33.42) v1(78.78,11.58) v1(78.78,10.94) v1(78.78,10.31) v1(78.78,9.67) v1(78.78,9.04) v1(78.77,3.32) v1(78.77,2.71) v1(78.77,2.08) v1(78.77,1.44) v1(78.77,0.81) v1(79.18,27.69) v1(79.18,27.03) v1(79.18,17.28) v1(79.4,44.19) v1(79.4,43.56) v1(79.4,42.92) v1(79.4,42.29) v1(79.4,41.68) v1(79.42,35.96) v1(79.42,35.33) v1(79.42,34.69) v1(79.42,34.06) v1(79.42,33.42) v1(79.42,29.89) v1(79.42,15.11) v1(79.42,11.58) v1(79.42,10.94) v1(79.42,10.31) v1(79.42,9.67) v1(79.42,9.04) v1(79.4,3.32) v1(79.4,2.71) v1(79.4,2.08) v1(79.4,1.44) v1(79.4,0.81) v1(79.58,26.6) v1(79.58,18.4) v1(79.86,27.17) v1(79.86,17.83) v1(80.04,44.19) v1(80.04,43.56) v1(80.04,42.92) v1(80.04,42.29) v1(80.04,41.68) v1(80.05,35.96) v1(80.05,35.33) v1(80.05,34.69) v1(80.05,34.06) v1(80.05,33.42) v1(79.97,27.81) v1(80.03,26.15) v1(80.03,18.85) v1(79.97,17.19) v1(80.05,11.58) v1(80.05,10.94) v1(80.05,10.31) v1(80.05,9.67) v1(80.05,9.04) v1(80.04,3.32) v1(80.04,2.71) v1(80.04,2.08) v1(80.04,1.44) v1(80.04,0.81) v1(80.1,28.44) v1(80.1,25.29) v1(80.1,19.71) v1(80.1,16.56) v1(80.26,29.05) v1(80.26,15.95) v1(80.31,26.72) v1(80.35,24.14) v1(80.34,22.5) v1(80.35,20.86) v1(80.31,18.28) v1(80.45,29.78) v1(80.42,27.36) v1(80.42,17.64) v1(80.45,15.22) v1(80.55,27.99) v1(80.55,24.84) v1(80.55,20.16) v1(80.55,17.01) v1(80.58,25.7) v1(80.58,19.3) v1(80.67,44.19) v1(80.67,43.56) v1(80.67,42.92) v1(80.67,42.29) v1(80.67,41.68) v1(80.69,35.96) v1(80.69,35.33) v1(80.69,34.69) v1(80.69,34.06) v1(80.69,33.42) v1(80.69,32.79) v1(80.69,32.15) v1(80.69,31.52) v1(80.69,30.88) v1(80.71,28.6) v1(80.71,16.4) v1(80.68,14.13) v1(80.69,13.48) v1(80.69,12.85) v1(80.69,12.21) v1(80.69,11.58) v1(80.69,10.94) v1(80.69,10.31) v1(80.69,9.67) v1(80.69,9.04) v1(80.67,3.32) v1(80.67,2.71) v1(80.67,2.08) v1(80.67,1.44) v1(80.67,0.81) v1(80.81,26.28) v1(80.81,18.72) v1(80.89,30.33) v1(80.94,29.19) v1(80.87,26.91) v1(80.96,22.5) v1(80.87,18.09) v1(80.94,15.81) v1(80.92,14.66) v1(81,27.54) v1(81.03,25.26) v1(81.01,24.38) v1(81.01,20.62) v1(81.03,19.74) v1(81,17.46) v1(81.16,28.15) v1(81.16,16.85) v1(81.23,29.76) v1(81.23,15.24) v1(81.31,44.19) v1(81.31,43.56) v1(81.31,42.92) v1(81.31,42.29) v1(81.31,41.68) v1(81.32,35.96) v1(81.32,35.33) v1(81.32,34.69) v1(81.32,34.06) v1(81.32,33.42) v1(81.32,32.79) v1(81.32,32.15) v1(81.31,25.83) v1(81.31,19.17) v1(81.32,12.85) v1(81.32,12.21) v1(81.32,11.58) v1(81.32,10.94) v1(81.32,10.31) v1(81.32,9.67) v1(81.32,9.04) v1(81.31,3.32) v1(81.31,2.71) v1(81.31,2.08) v1(81.31,1.44) v1(81.31,0.81) v1(81.39,28.75) v1(81.45,27.09) v1(81.37,26.46) v1(81.37,18.54) v1(81.45,17.91) v1(81.39,16.25) v1(81.48,24.8) v1(81.54,22.97) v1(81.54,22.03) v1(81.48,20.2) v1(81.57,31.2) v1(81.6,30.28) v1(81.61,27.7) v1(81.61,17.3) v1(81.6,14.72) v1(81.57,13.8) v1(81.68,29.31) v1(81.68,15.69) v1(81.83,28.3) v1(81.81,25.35) v1(81.81,19.65) v1(81.83,16.7) v1(81.94,44.19) v1(81.94,43.56) v1(81.94,42.92) v1(81.94,42.29) v1(81.94,41.68) v1(81.96,12.21) v1(81.96,11.58) v1(81.96,10.94) v1(81.96,10.31) v1(81.96,9.67) v1(81.96,9.04) v1(81.94,3.32) v1(81.94,2.71) v1(81.94,2.08) v1(81.94,1.44) v1(81.94,0.81) v1(82.02,31.65) v1(82.02,30.75) v1(82.04,29.83) v1(82.02,26.59) v1(81.98,25.96) v1(82,22.5) v1(81.98,19.04) v1(82.02,18.41) v1(82.04,15.17) v1(82.02,14.25) v1(82.02,13.35) v1(82.13,28.86) v1(82.13,27.22) v1(82.06,23.32) v1(82.06,21.68) v1(82.13,17.78) v1(82.13,16.14) v1(82.32,27.82) v1(82.32,17.18) v1(82.46,32.1) v1(82.46,31.2) v1(82.47,30.3) v1(82.49,29.38) v1(82.53,23.76) v1(82.52,22.87) v1(82.52,22.13) v1(82.53,21.24) v1(82.49,15.62) v1(82.47,14.7) v1(82.46,13.8) v1(82.46,12.9) v1(82.58,44.19) v1(82.58,43.56) v1(82.58,42.92) v1(82.58,42.29) v1(82.58,41.68) v1(82.6,28.4) v1(82.6,16.6) v1(82.58,3.32) v1(82.58,2.71) v1(82.58,2.08) v1(82.58,1.44) v1(82.58,0.81) v1(82.91,32.55) v1(82.91,31.65) v1(82.91,30.75) v1(82.91,29.86) v1(82.95,28.93) v1(82.91,24.27) v1(82.91,20.73) v1(82.95,16.07) v1(82.91,15.15) v1(82.91,14.25) v1(82.91,13.35) v1(82.91,12.45) v1(82.98,23.31) v1(83.02,22.5) v1(82.98,21.69) v1(83.21,44.19) v1(83.21,43.56) v1(83.21,42.92) v1(83.21,42.29) v1(83.21,41.68) v1(83.19,24.83) v1(83.19,20.17) v1(83.21,3.32) v1(83.21,2.71) v1(83.21,2.08) v1(83.21,1.44) v1(83.21,0.81) v1(83.36,33) v1(83.36,32.1) v1(83.36,31.2) v1(83.36,30.3) v1(83.36,29.41) v1(83.38,25.44) v1(83.37,23.81) v1(83.37,21.19) v1(83.38,19.56) v1(83.36,15.59) v1(83.36,14.7) v1(83.36,13.8) v1(83.36,12.9) v1(83.36,12) v1(83.52,26.7) v1(83.46,26.07) v1(83.47,23) v1(83.47,22) v1(83.46,18.93) v1(83.52,18.3) v1(83.71,27.31) v1(83.68,24.36) v1(83.68,20.64) v1(83.71,17.69) v1(83.85,44.19) v1(83.86,43.56) v1(83.86,42.92) v1(83.86,42.29) v1(83.86,41.68) v1(83.81,33.45) v1(83.81,32.55) v1(83.81,31.65) v1(83.81,30.75) v1(83.81,29.85) v1(83.81,15.15) v1(83.81,14.25) v1(83.81,13.35) v1(83.81,12.45) v1(83.81,11.55) v1(83.86,3.32) v1(83.86,2.71) v1(83.86,2.08) v1(83.86,1.44) v1(83.85,0.81) v1(83.91,24.95) v1(83.87,23.47) v1(83.88,22.5) v1(83.87,21.53) v1(83.91,20.05) v1(84,27.87) v1(84.05,25.57) v1(84.05,19.43) v1(84,17.13) v1(84.02,4.16) v1(84.1,26.21) v1(84.1,18.79) v1(84.26,33.9) v1(84.26,33) v1(84.26,32.1) v1(84.26,31.2) v1(84.26,30.3) v1(84.21,26.83) v1(84.23,23.94) v1(84.23,21.06) v1(84.21,18.17) v1(84.26,14.7) v1(84.26,13.8) v1(84.26,12.9) v1(84.26,12) v1(84.26,11.1) v1(84.33,23.03) v1(84.33,21.97) v1(84.41,28.36) v1(84.37,24.51) v1(84.37,20.49) v1(84.41,16.64) v1(84.54,43.16) v1(84.51,42.23) v1(84.49,41.31) v1(84.47,27.41) v1(84.51,25.13) v1(84.51,19.87) v1(84.47,17.59) v1(84.46,4.61) v1(84.49,3.69) v1(84.51,2.77) v1(84.54,1.84) v1(84.57,44.08) v1(84.64,25.76) v1(84.64,19.24) v1(84.57,0.92) v1(84.71,34.35) v1(84.71,33.45) v1(84.71,32.55) v1(84.71,31.65) v1(84.71,30.75) v1(84.74,26.39) v1(84.69,23.49) v1(84.71,22.48) v1(84.69,21.51) v1(84.74,18.61) v1(84.71,14.25) v1(84.71,13.35) v1(84.71,12.45) v1(84.71,11.55) v1(84.71,10.65) v1(84.85,28.81) v1(84.86,27.91) v1(84.84,24.06) v1(84.84,20.94) v1(84.86,17.09) v1(84.85,16.19) v1(84.94,40.86) v1(84.92,26.97) v1(84.96,24.68) v1(84.96,20.32) v1(84.92,18.03) v1(84.91,5.06) v1(84.94,4.14) v1(85.01,43.63) v1(84.99,42.71) v1(84.96,41.78) v1(84.96,3.22) v1(84.99,2.29) v1(85.01,1.37) v1(85.16,34.79) v1(85.16,33.9) v1(85.16,33) v1(85.16,32.1) v1(85.16,31.2) v1(85.09,25.31) v1(85.11,23.02) v1(85.11,21.98) v1(85.09,19.69) v1(85.16,13.8) v1(85.16,12.9) v1(85.16,12) v1(85.16,11.1) v1(85.16,10.21) v1(85.19,25.94) v1(85.19,19.06) v1(85.3,29.26) v1(85.3,28.36) v1(85.31,27.47) v1(85.34,23.61) v1(85.34,21.39) v1(85.31,17.53) v1(85.3,16.64) v1(85.3,15.74) v1(85.44,42.26) v1(85.41,41.34) v1(85.39,40.41) v1(85.37,26.52) v1(85.41,24.23) v1(85.41,20.77) v1(85.37,18.48) v1(85.36,5.51) v1(85.39,4.59) v1(85.41,3.66) v1(85.44,2.74) v1(85.46,43.18) v1(85.53,24.86) v1(85.53,20.14) v1(85.46,1.82) v1(85.61,35.24) v1(85.61,34.35) v1(85.61,33.45) v1(85.61,32.55) v1(85.61,31.65) v1(85.64,25.49) v1(85.64,19.51) v1(85.61,13.35) v1(85.61,12.45) v1(85.61,11.55) v1(85.61,10.65) v1(85.61,9.76) v1(85.75,29.71) v1(85.75,28.81) v1(85.75,16.19) v1(85.75,15.29) v1(85.84,39.96) v1(85.76,27.92) v1(85.76,27.02) v1(85.82,26.07) v1(85.82,18.93) v1(85.76,17.98) v1(85.76,17.08) v1(85.81,5.96) v1(85.84,5.04) v1(85.91,42.73) v1(85.89,41.81) v1(85.86,40.89) v1(85.86,4.11) v1(85.89,3.19) v1(85.91,2.27) v1(86.06,35.69) v1(86.06,34.79) v1(86.06,33.9) v1(86.06,33) v1(86.06,32.1) v1(86.06,12.9) v1(86.06,12) v1(86.06,11.1) v1(86.06,10.21) v1(86.06,9.31) v1(86.2,30.16) v1(86.2,29.26) v1(86.21,28.37) v1(86.21,27.47) v1(86.21,26.57) v1(86.21,18.43) v1(86.21,17.53) v1(86.21,16.63) v1(86.2,15.74) v1(86.2,14.84) v1(86.26,6.41) v1(86.34,41.36) v1(86.31,40.44) v1(86.29,39.51) v1(86.29,5.49) v1(86.31,4.56) v1(86.34,3.64) v1(86.36,42.28) v1(86.36,2.72) v1(86.51,36.14) v1(86.51,35.24) v1(86.51,34.35) v1(86.51,33.45) v1(86.51,32.55) v1(86.51,12.45) v1(86.51,11.55) v1(86.51,10.66) v1(86.51,9.76) v1(86.51,8.86) v1(86.65,30.61) v1(86.65,29.71) v1(86.66,28.82) v1(86.66,27.92) v1(86.66,27.02) v1(86.66,17.98) v1(86.66,17.08) v1(86.66,16.18) v1(86.65,15.29) v1(86.65,14.39) v1(86.76,39.99) v1(86.73,39.06) v1(86.71,6.86) v1(86.73,5.94) v1(86.76,5.01) v1(86.81,41.84) v1(86.79,40.91) v1(86.79,4.09) v1(86.81,3.16) v1(86.95,36.59) v1(86.95,35.69) v1(86.96,34.79) v1(86.96,33.9) v1(86.96,33) v1(86.96,12) v1(86.96,11.1) v1(86.96,10.21) v1(86.95,9.31) v1(86.95,8.41) v1(87.13,31.08) v1(87.1,30.16) v1(87.11,29.27) v1(87.11,28.37) v1(87.11,27.47) v1(87.11,17.53) v1(87.11,16.63) v1(87.11,15.73) v1(87.1,14.84) v1(87.13,13.92) v1(87.16,7.31) v1(87.26,41.39) v1(87.23,40.46) v1(87.21,39.54) v1(87.18,38.62) v1(87.18,6.38) v1(87.21,5.46) v1(87.23,4.54) v1(87.26,3.61) v1(87.4,37.04) v1(87.4,36.14) v1(87.4,35.24) v1(87.4,34.35) v1(87.4,33.45) v1(87.4,11.55) v1(87.4,10.66) v1(87.4,9.76) v1(87.4,8.86) v1(87.4,7.96) v1(87.56,29.71) v1(87.56,28.82) v1(87.56,27.92) v1(87.56,17.08) v1(87.56,16.18) v1(87.56,15.29) v1(87.66,39.09) v1(87.63,38.17) v1(87.6,31.56) v1(87.57,30.63) v1(87.57,14.37) v1(87.6,13.44) v1(87.63,6.83) v1(87.66,5.91) v1(87.71,40.94) v1(87.68,40.01) v1(87.68,4.99) v1(87.71,4.06) v1(87.85,36.59) v1(87.85,35.69) v1(87.85,33.9) v1(87.85,11.1) v1(87.85,9.31) v1(87.85,8.41) v1(87.94,37.58) v1(87.94,7.42) v1(88.05,31.11) v1(88.03,30.19) v1(88.01,29.27) v1(88.01,28.37) v1(88.01,16.63) v1(88.01,15.74) v1(88.03,14.81) v1(88.05,13.89) v1(88.16,40.49) v1(88.13,39.56) v1(88.11,38.64) v1(88.07,32.03) v1(88.07,12.97) v1(88.11,6.36) v1(88.13,5.44) v1(88.16,4.51) v1(88.3,36.14) v1(88.3,8.86) v1(88.45,38.09) v1(88.39,37.13) v1(88.46,28.82) v1(88.46,16.18) v1(88.39,7.87) v1(88.45,6.91) v1(88.55,32.51) v1(88.52,31.58) v1(88.51,30.66) v1(88.48,29.74) v1(88.48,15.26) v1(88.51,14.34) v1(88.52,13.42) v1(88.55,12.49) v1(88.61,40.04) v1(88.58,39.12) v1(88.58,5.88) v1(88.61,4.96) v1(88.7,35.64) v1(88.7,9.36) v1(88.84,36.68) v1(88.84,8.32) v1(88.9,37.64) v1(88.96,30.21) v1(88.93,29.29) v1(88.93,15.71) v1(88.96,14.79) v1(88.9,7.36) v1(89.06,39.59) v1(89.03,38.67) v1(89.02,32.98) v1(89,32.06) v1(88.98,31.14) v1(88.98,13.86) v1(89,12.94) v1(89.02,12.02) v1(89.03,6.33) v1(89.06,5.41) v1(89.15,35.19) v1(89.15,9.81) v1(89.18,36.12) v1(89.18,8.88) v1(89.35,37.19) v1(89.35,7.81) v1(89.46,31.61) v1(89.43,30.69) v1(89.41,29.76) v1(89.41,15.24) v1(89.43,14.31) v1(89.46,13.39) v1(89.51,39.14) v1(89.48,38.22) v1(89.5,33.46) v1(89.47,32.53) v1(89.47,12.47) v1(89.5,11.55) v1(89.48,6.78) v1(89.51,5.86) v1(89.65,36.59) v1(89.62,35.67) v1(89.62,9.33) v1(89.65,8.41) v1(89.95,38.69) v1(89.93,37.77) v1(89.95,33.01) v1(89.93,32.09) v1(89.91,31.16) v1(89.88,30.24) v1(89.88,14.76) v1(89.91,13.84) v1(89.93,12.91) v1(89.95,11.99) v1(89.93,7.23) v1(89.95,6.31) v1(89.97,33.93) v1(89.97,11.07) v1(90.1,36.14) v1(90.1,8.86) v1(90.35,30.71) v1(90.35,14.29) v1(90.4,38.24) v1(90.45,34.4) v1(90.42,33.48) v1(90.41,32.56) v1(90.38,31.64) v1(90.38,13.36) v1(90.41,12.44) v1(90.42,11.52) v1(90.45,10.6) v1(90.4,6.76) v1(90.85,37.79) v1(90.85,32.11) v1(90.83,31.19) v1(90.83,13.81) v1(90.85,12.89) v1(90.85,7.21) v1(90.92,34.88) v1(90.9,33.95) v1(90.88,33.04) v1(90.88,11.96) v1(90.9,11.05) v1(90.92,10.12) v1(91.3,37.34) v1(91.35,33.51) v1(91.33,32.59) v1(91.3,31.66) v1(91.3,13.34) v1(91.33,12.41) v1(91.35,11.49) v1(91.3,7.66) v1(91.4,35.35) v1(91.37,34.43) v1(91.37,10.57) v1(91.4,9.65) v1(91.84,34.9) v1(91.83,33.98) v1(91.8,33.06) v1(91.78,32.14) v1(91.78,12.86) v1(91.8,11.94) v1(91.83,11.02) v1(91.84,10.1) v1(91.87,35.83) v1(91.87,9.17) v1(92.25,32.61) v1(92.25,12.39) v1(92.34,36.3) v1(92.32,35.38) v1(92.3,34.46) v1(92.28,33.54) v1(92.28,11.46) v1(92.3,10.54) v1(92.32,9.62) v1(92.34,8.7) v1(92.75,34.01) v1(92.73,33.09) v1(92.73,11.91) v1(92.75,10.99) v1(92.79,35.85) v1(92.77,34.93) v1(92.77,32.23) v1(92.77,12.77) v1(92.77,10.07) v1(92.79,9.15) v1(93.24,35.4) v1(93.22,34.48) v1(93.2,33.56) v1(93.22,32.68) v1(93.22,31.79) v1(93.22,13.21) v1(93.22,12.32) v1(93.2,11.44) v1(93.22,10.52) v1(93.24,9.6) v1(93.69,34.95) v1(93.67,34.03) v1(93.67,33.13) v1(93.67,32.23) v1(93.67,31.34) v1(93.67,13.66) v1(93.67,12.77) v1(93.67,11.87) v1(93.67,10.97) v1(93.69,10.05) v1(94.14,34.51) v1(94.12,33.58) v1(94.12,32.68) v1(94.12,31.79) v1(94.12,30.89) v1(94.12,14.11) v1(94.12,13.21) v1(94.12,12.32) v1(94.12,11.42) v1(94.14,10.49) v1(94.59,34.06) v1(94.56,33.13) v1(94.56,32.23) v1(94.56,31.34) v1(94.56,30.44) v1(94.56,14.56) v1(94.56,13.66) v1(94.56,12.77) v1(94.56,11.87) v1(94.59,10.94) v1(95.04,33.61) v1(95.01,32.68) v1(95.01,31.79) v1(95.01,30.89) v1(95.01,29.99) v1(95.01,15.01) v1(95.01,14.11) v1(95.01,13.21) v1(95.01,12.32) v1(95.04,11.39) v1(95.49,33.16) v1(95.46,32.23) v1(95.46,31.34) v1(95.46,30.44) v1(95.46,29.54) v1(95.46,15.46) v1(95.46,14.56) v1(95.46,13.66) v1(95.46,12.77) v1(95.49,11.84) v1(95.94,32.71) v1(95.91,31.79) v1(95.91,30.89) v1(95.91,29.99) v1(95.91,29.09) v1(95.91,15.91) v1(95.91,15.01) v1(95.91,14.11) v1(95.91,13.21) v1(95.94,12.29) v1(96.36,31.34) v1(96.36,30.44) v1(96.36,29.54) v1(96.36,15.46) v1(96.36,14.56) v1(96.36,13.66) v1(96.39,32.26) v1(96.39,12.74) v1(96.65,28.86) v1(96.65,28.22) v1(96.65,27.58) v1(96.65,26.95) v1(96.65,26.31) v1(96.65,25.68) v1(96.65,25.04) v1(96.65,24.41) v1(96.65,23.77) v1(96.65,23.14) v1(96.65,22.5) v1(96.65,21.87) v1(96.65,21.23) v1(96.65,20.6) v1(96.65,19.96) v1(96.65,19.33) v1(96.65,18.69) v1(96.65,18.06) v1(96.65,17.42) v1(96.65,16.79) v1(96.65,16.16) v1(96.84,31.81) v1(96.81,30.89) v1(96.81,29.99) v1(96.81,15.01) v1(96.81,14.11) v1(96.84,13.19) v1(97.26,30.44) v1(97.26,29.54) v1(97.26,15.46) v1(97.26,14.56) v1(97.28,31.36) v1(97.29,28.85) v1(97.29,28.22) v1(97.29,27.58) v1(97.29,26.95) v1(97.29,26.31) v1(97.29,25.68) v1(97.29,25.04) v1(97.29,24.41) v1(97.29,23.77) v1(97.29,23.14) v1(97.29,22.5) v1(97.29,21.87) v1(97.29,21.23) v1(97.29,20.6) v1(97.29,19.96) v1(97.29,19.33) v1(97.29,18.69) v1(97.29,18.06) v1(97.29,17.42) v1(97.29,16.79) v1(97.29,16.15) v1(97.28,13.64) v1(97.73,30.91) v1(97.71,29.99) v1(97.71,15.01) v1(97.73,14.09) v1(97.92,28.85) v1(97.92,28.22) v1(97.92,27.58) v1(97.92,26.95) v1(97.92,26.31) v1(97.92,25.68) v1(97.92,25.04) v1(97.92,24.41) v1(97.92,23.77) v1(97.92,23.14) v1(97.92,22.5) v1(97.92,21.87) v1(97.92,21.23) v1(97.92,20.6) v1(97.92,19.96) v1(97.92,19.33) v1(97.92,18.69) v1(97.92,18.06) v1(97.92,17.42) v1(97.92,16.79) v1(97.92,16.15) v1(98.16,29.54) v1(98.16,15.46) v1(98.18,30.46) v1(98.18,14.54) v1(98.56,28.85) v1(98.56,28.22) v1(98.56,27.58) v1(98.56,26.95) v1(98.56,26.31) v1(98.56,25.68) v1(98.56,25.04) v1(98.56,24.41) v1(98.56,23.77) v1(98.56,23.14) v1(98.56,22.5) v1(98.56,21.87) v1(98.56,21.23) v1(98.56,20.6) v1(98.56,19.96) v1(98.56,19.33) v1(98.56,18.69) v1(98.56,18.06) v1(98.56,17.42) v1(98.56,16.79) v1(98.56,16.15) v1(98.63,30.01) v1(98.63,14.99) v1(99.08,29.57) v1(99.08,15.43) v1(99.19,28.85) v1(99.19,28.22) v1(99.19,27.58) v1(99.19,26.95) v1(99.19,26.31) v1(99.19,25.68) v1(99.19,25.04) v1(99.19,24.41) v1(99.19,23.77) v1(99.19,23.14) v1(99.19,22.5) v1(99.19,21.87) v1(99.19,21.23) v1(99.19,20.6) v1(99.19,19.96) v1(99.19,19.33) v1(99.19,18.69) v1(99.19,18.06) v1(99.19,17.42) v1(99.19,16.79) v1(99.19,16.15) v2(36.26,23.52) v2(36.26,22.5) v2(36.26,21.48) v2(37.28,23.52) v2(37.28,21.48) v2(38.29,23.52) v2(38.29,22.5) v2(38.29,21.48) v2(57.49,10.9) v2(57.49,10.27) v2(58.25,10.9) v2(58.25,10.27) v2(59.01,10.9) v2(59.59,22.01) v2(59.59,20.99) v2(59.59,20) v2(59.59,18.98) v2(59.59,17.97) v2(60.61,22.01) v2(60.61,20.99) v2(60.61,20) v2(60.61,18.98) v2(60.61,17.97) v2(61.62,22.01) v2(61.62,20.99) v2(61.62,20) v2(61.62,18.98) v2(62.64,22.01) v2(62.64,20.99) v2(62.64,20) v2(62.64,18.98) v2(62.64,17.97) v2(63.67,22.01) v2(63.67,20.99) v2(63.67,20) v2(63.67,18.98) v2(63.67,17.97) v2(78.31,22.5)
